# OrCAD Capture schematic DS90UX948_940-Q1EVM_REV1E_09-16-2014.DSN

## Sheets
1 08. Revision History: title: Revision History; rev: 1E; note: DS90UBUH948_940-Q1EVM
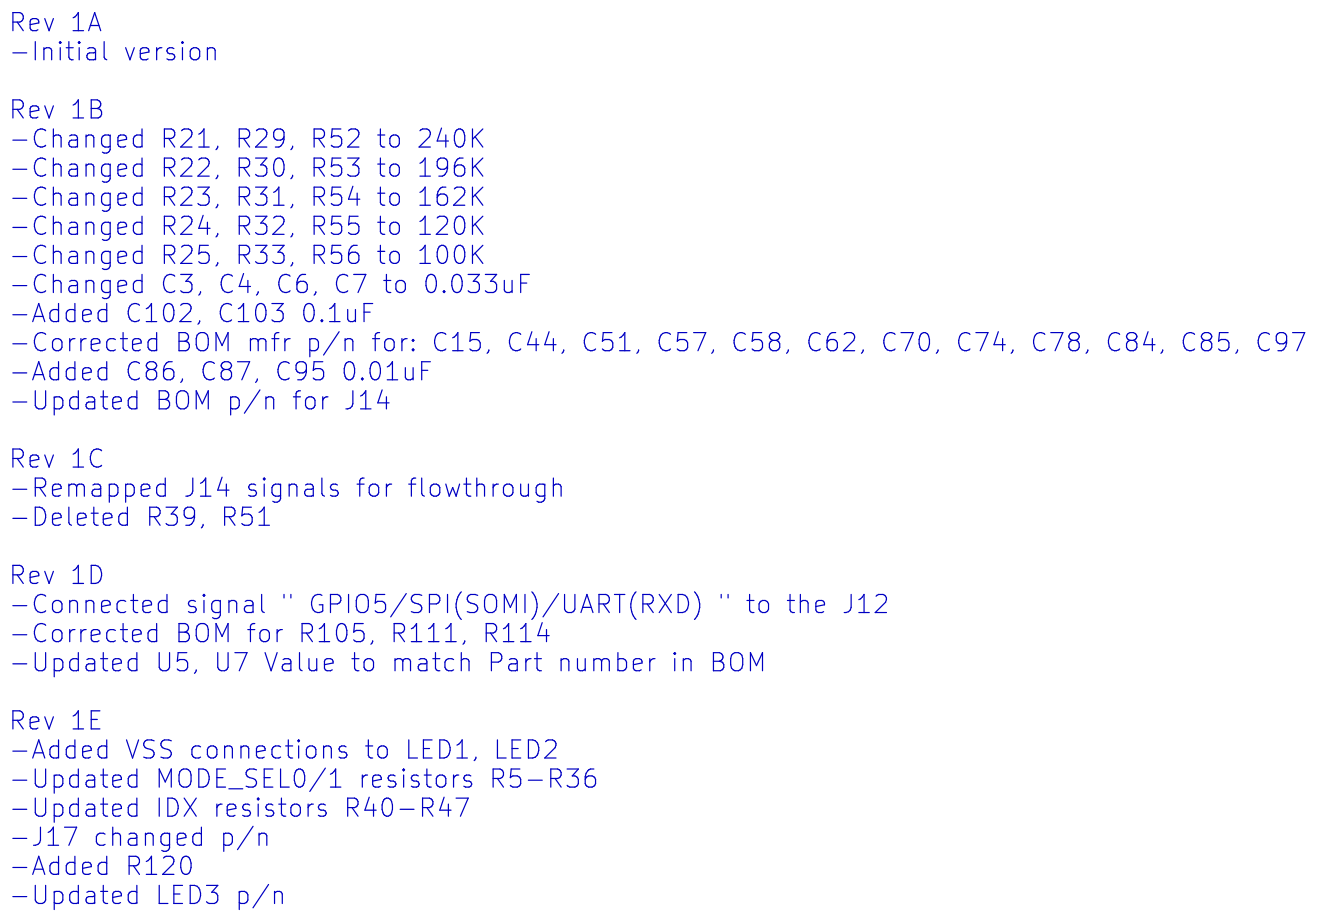
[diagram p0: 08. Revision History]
2 02. Block Diagram: title: Block Diagram
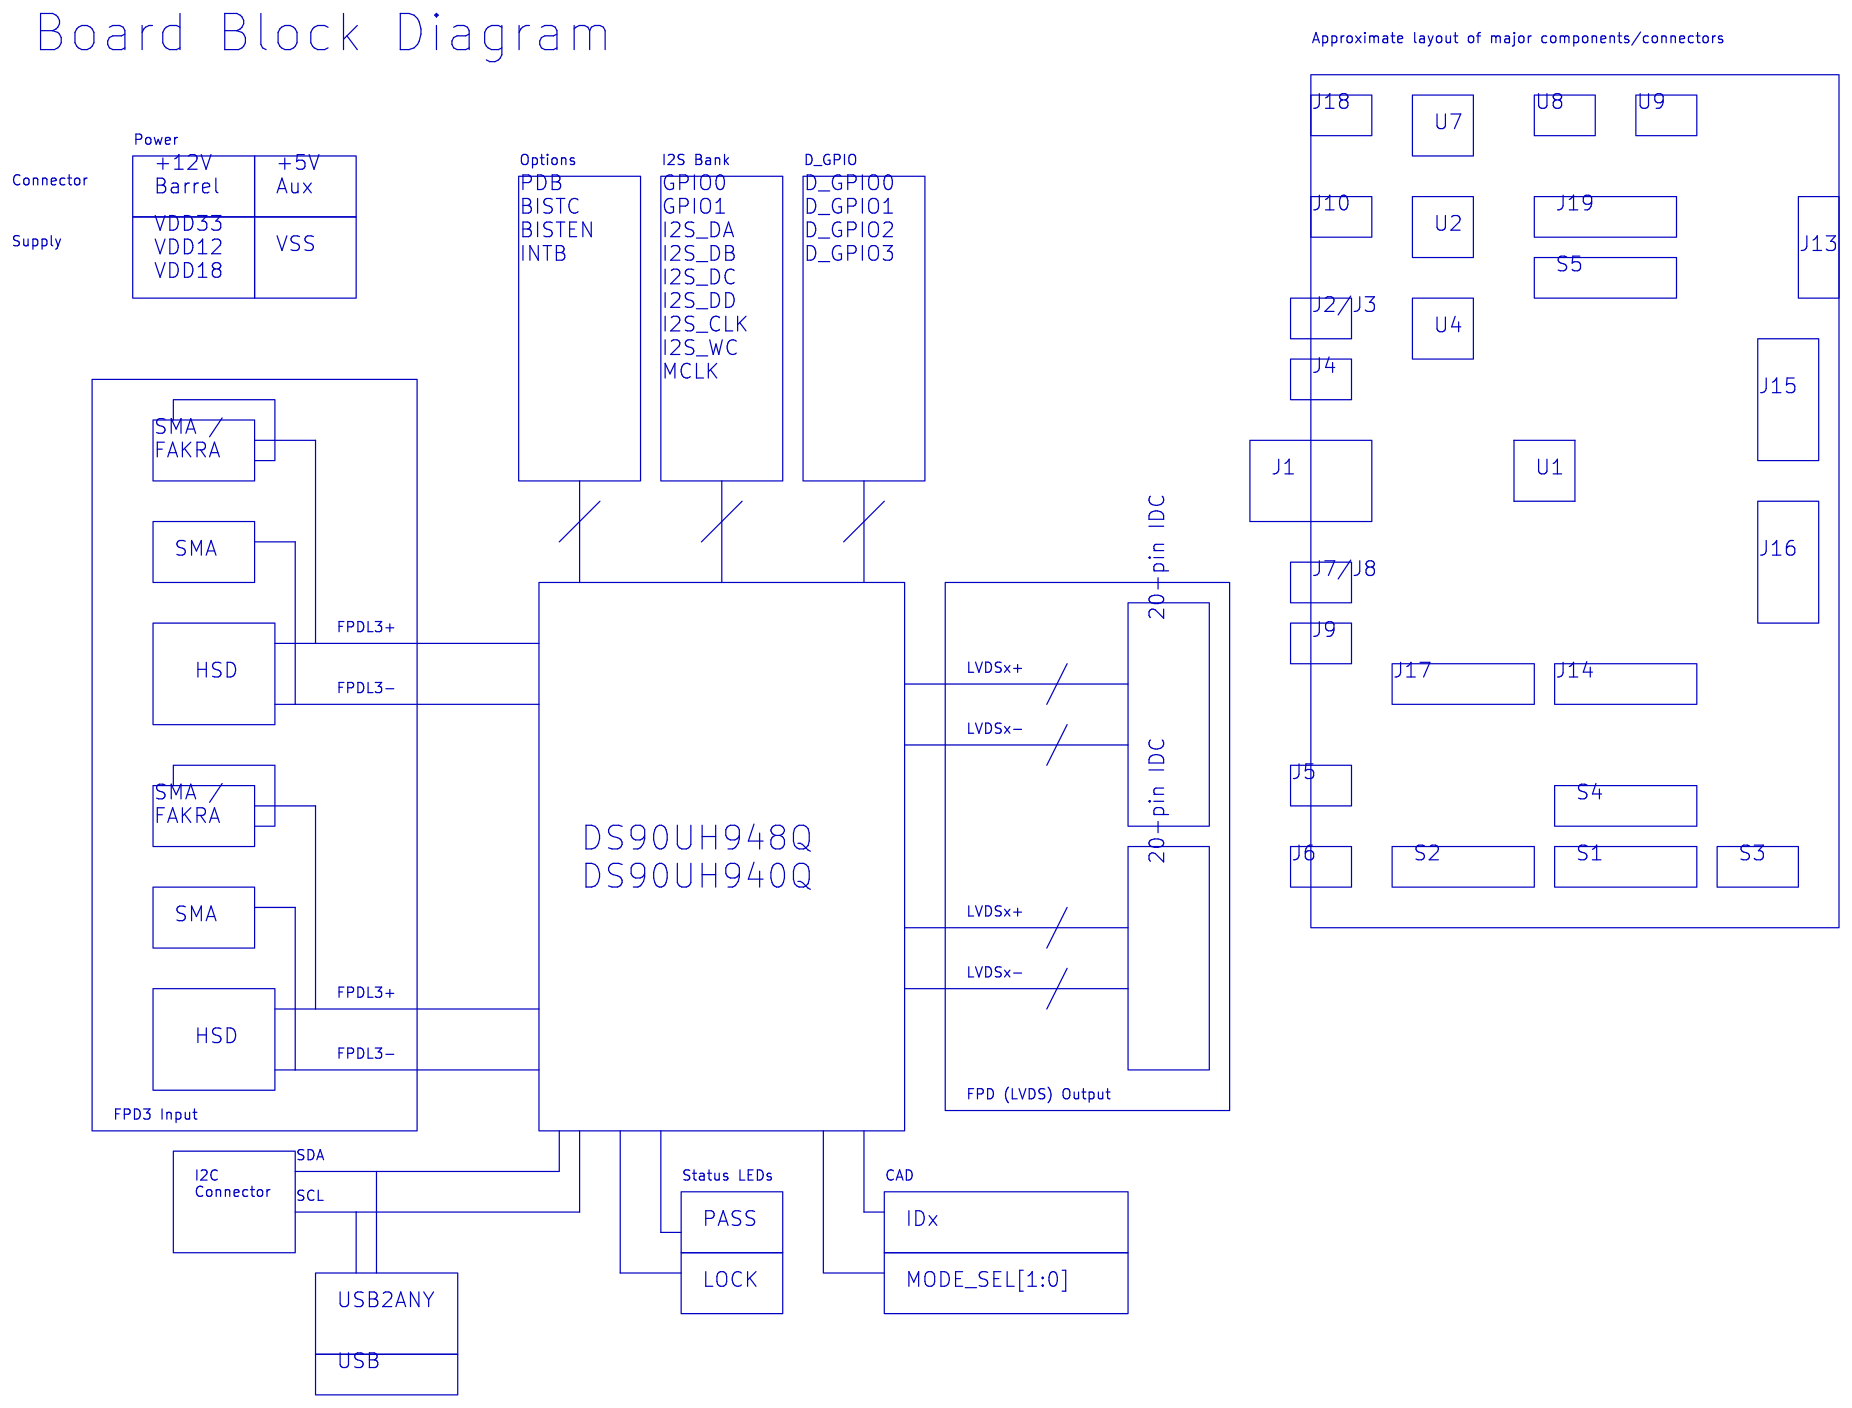
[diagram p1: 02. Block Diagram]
3 01. Board Stackup: title: Board Stackup
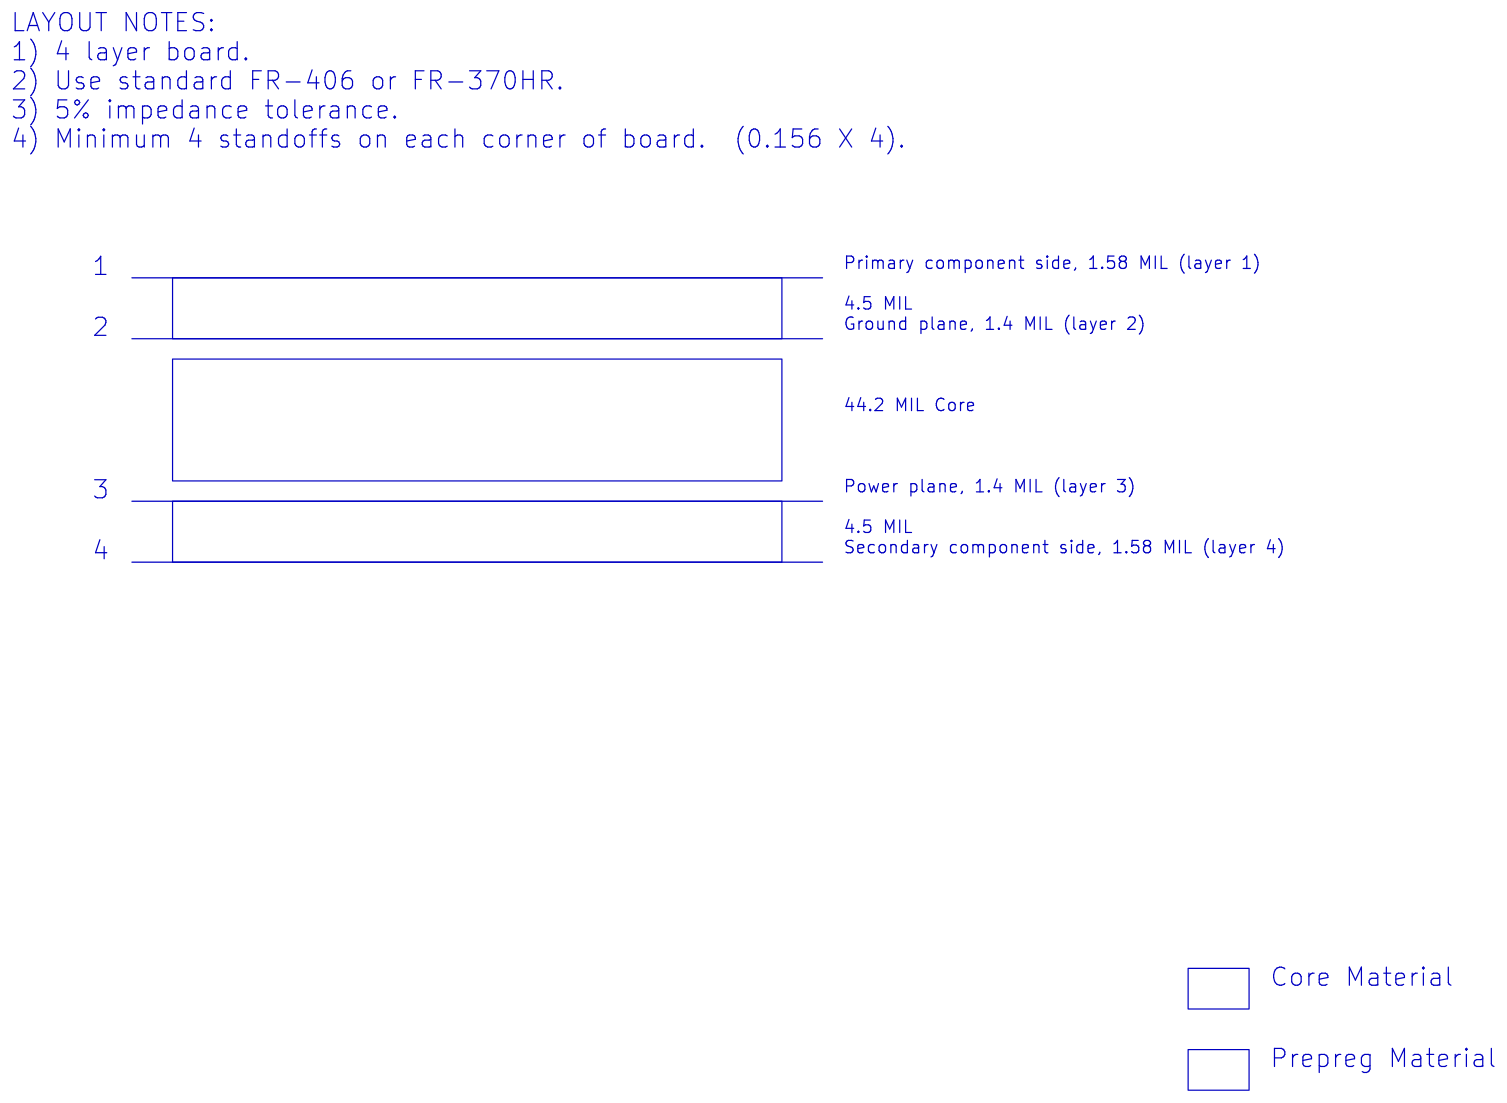
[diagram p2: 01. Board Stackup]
4 03. DS90UH948Q: size B; title: DS90UBUH948
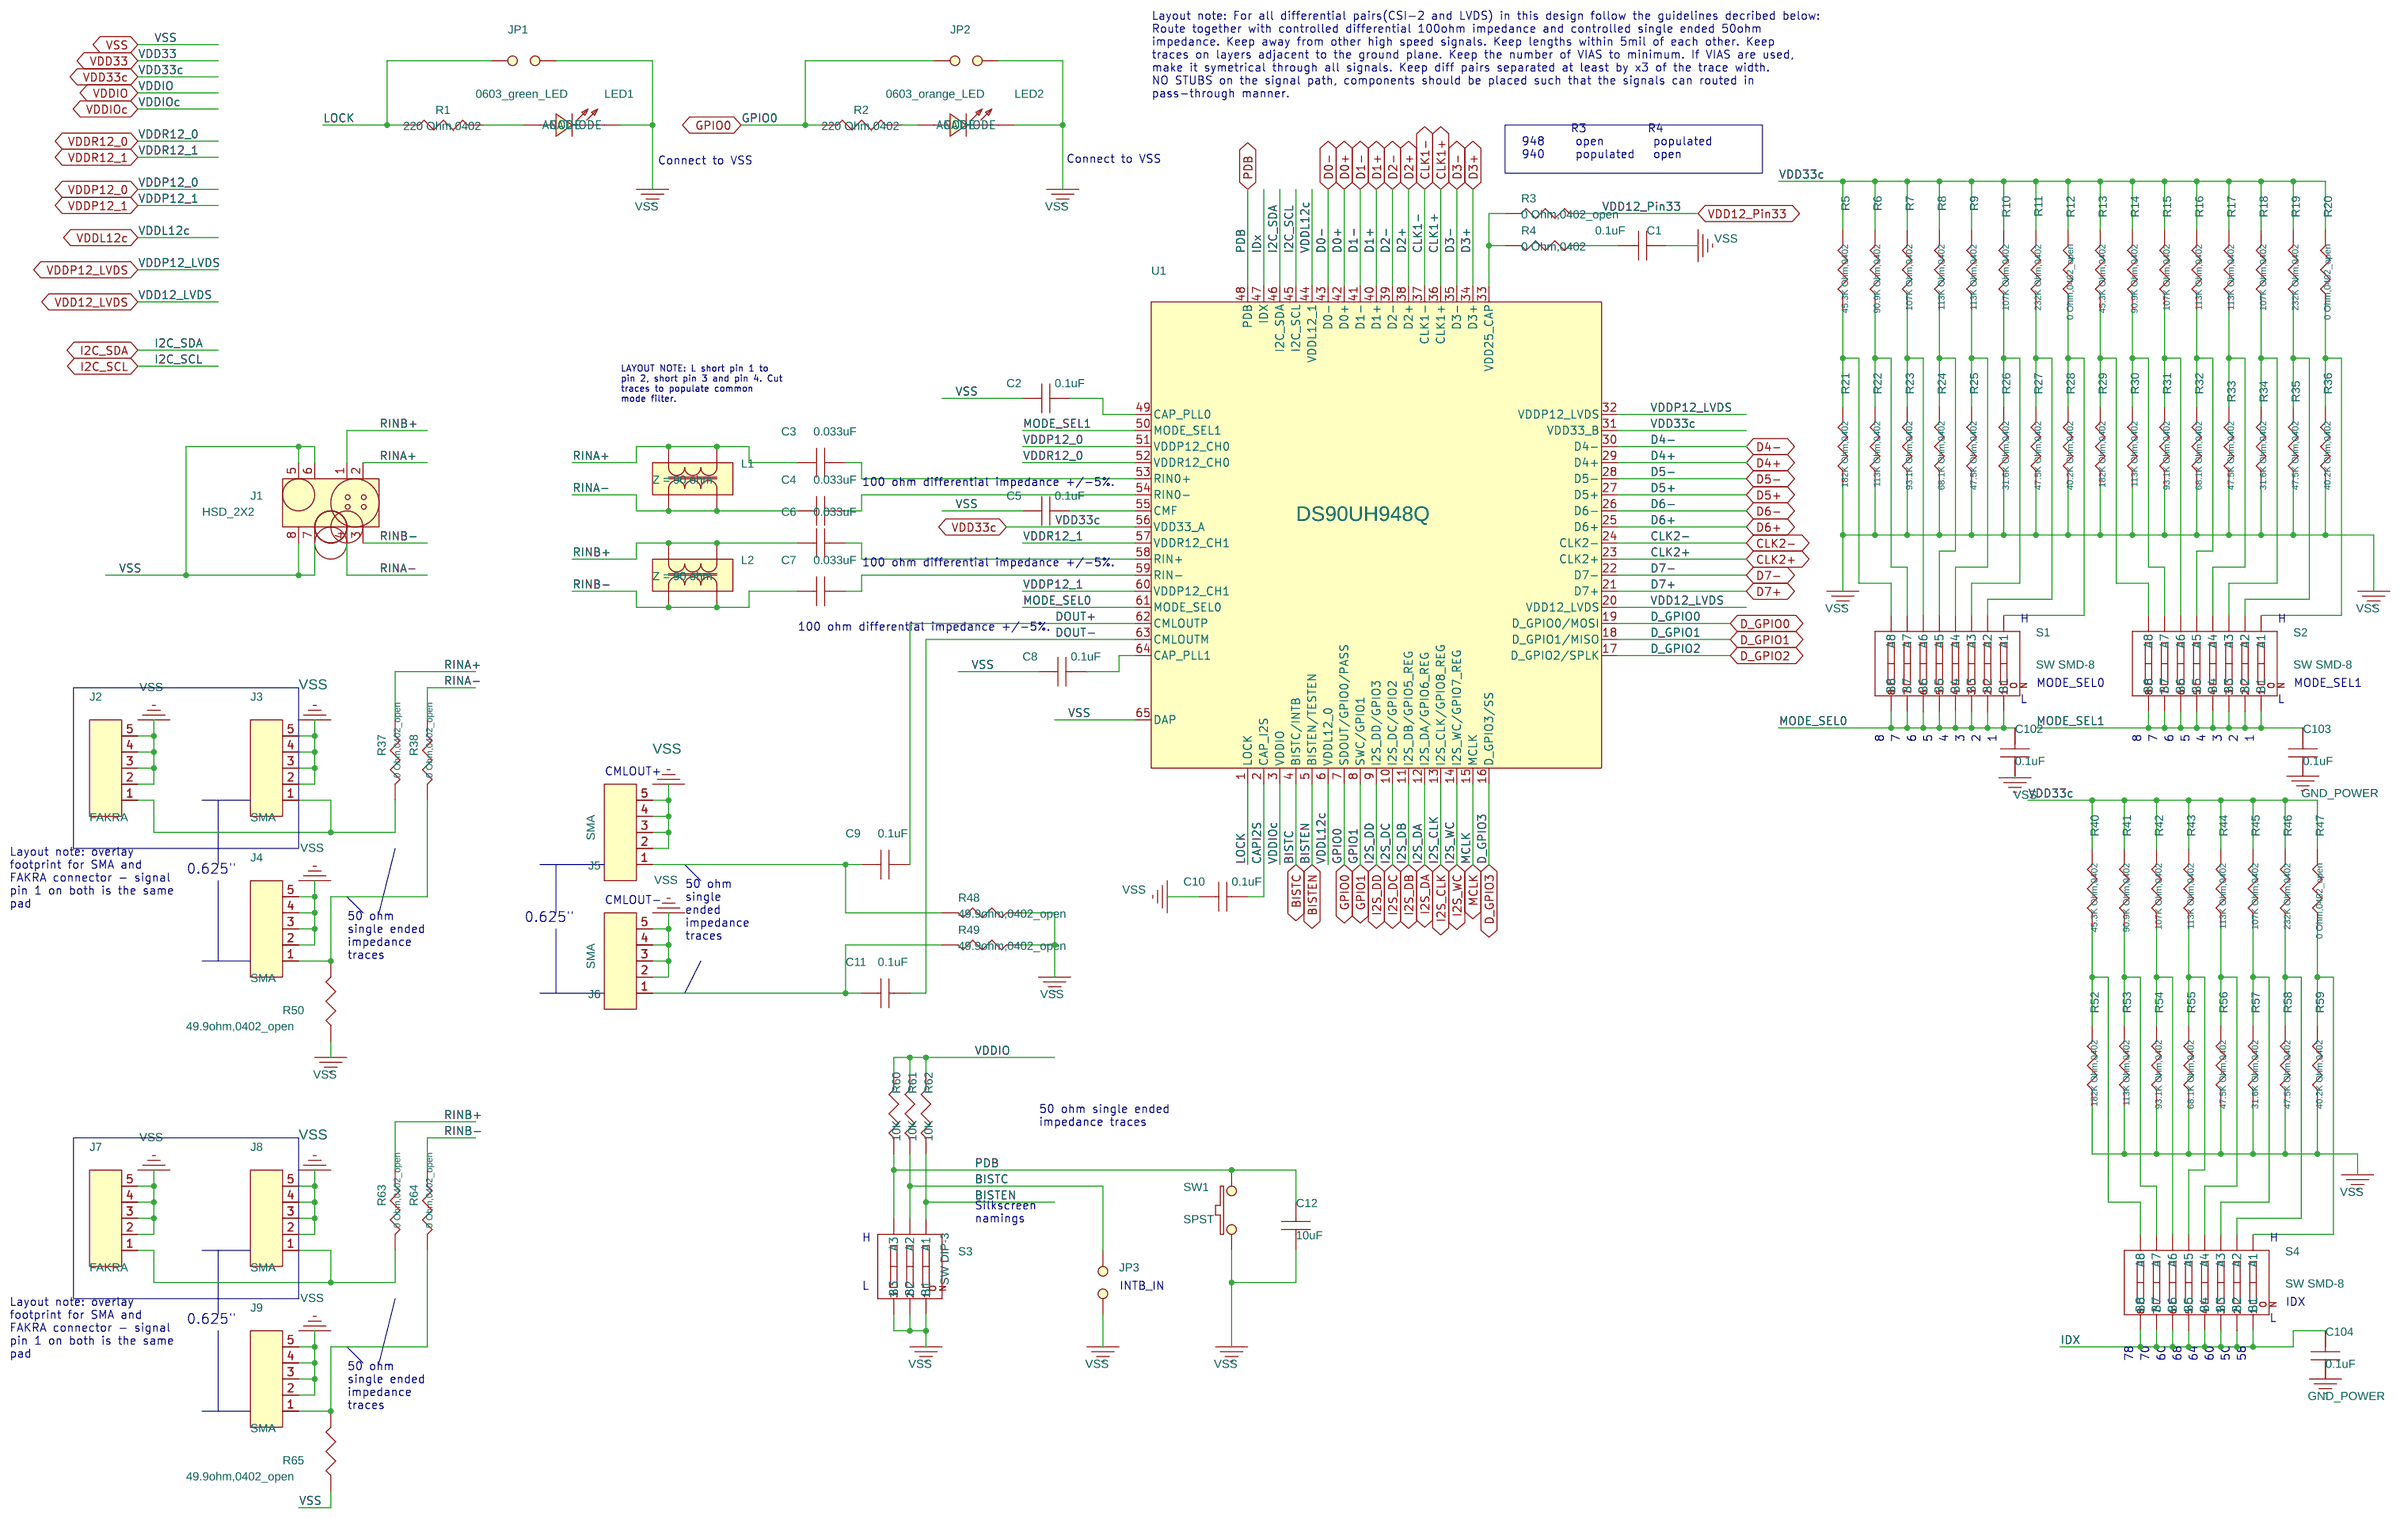
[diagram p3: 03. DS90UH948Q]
5 04. USB Controller: size C; title: USB Controller
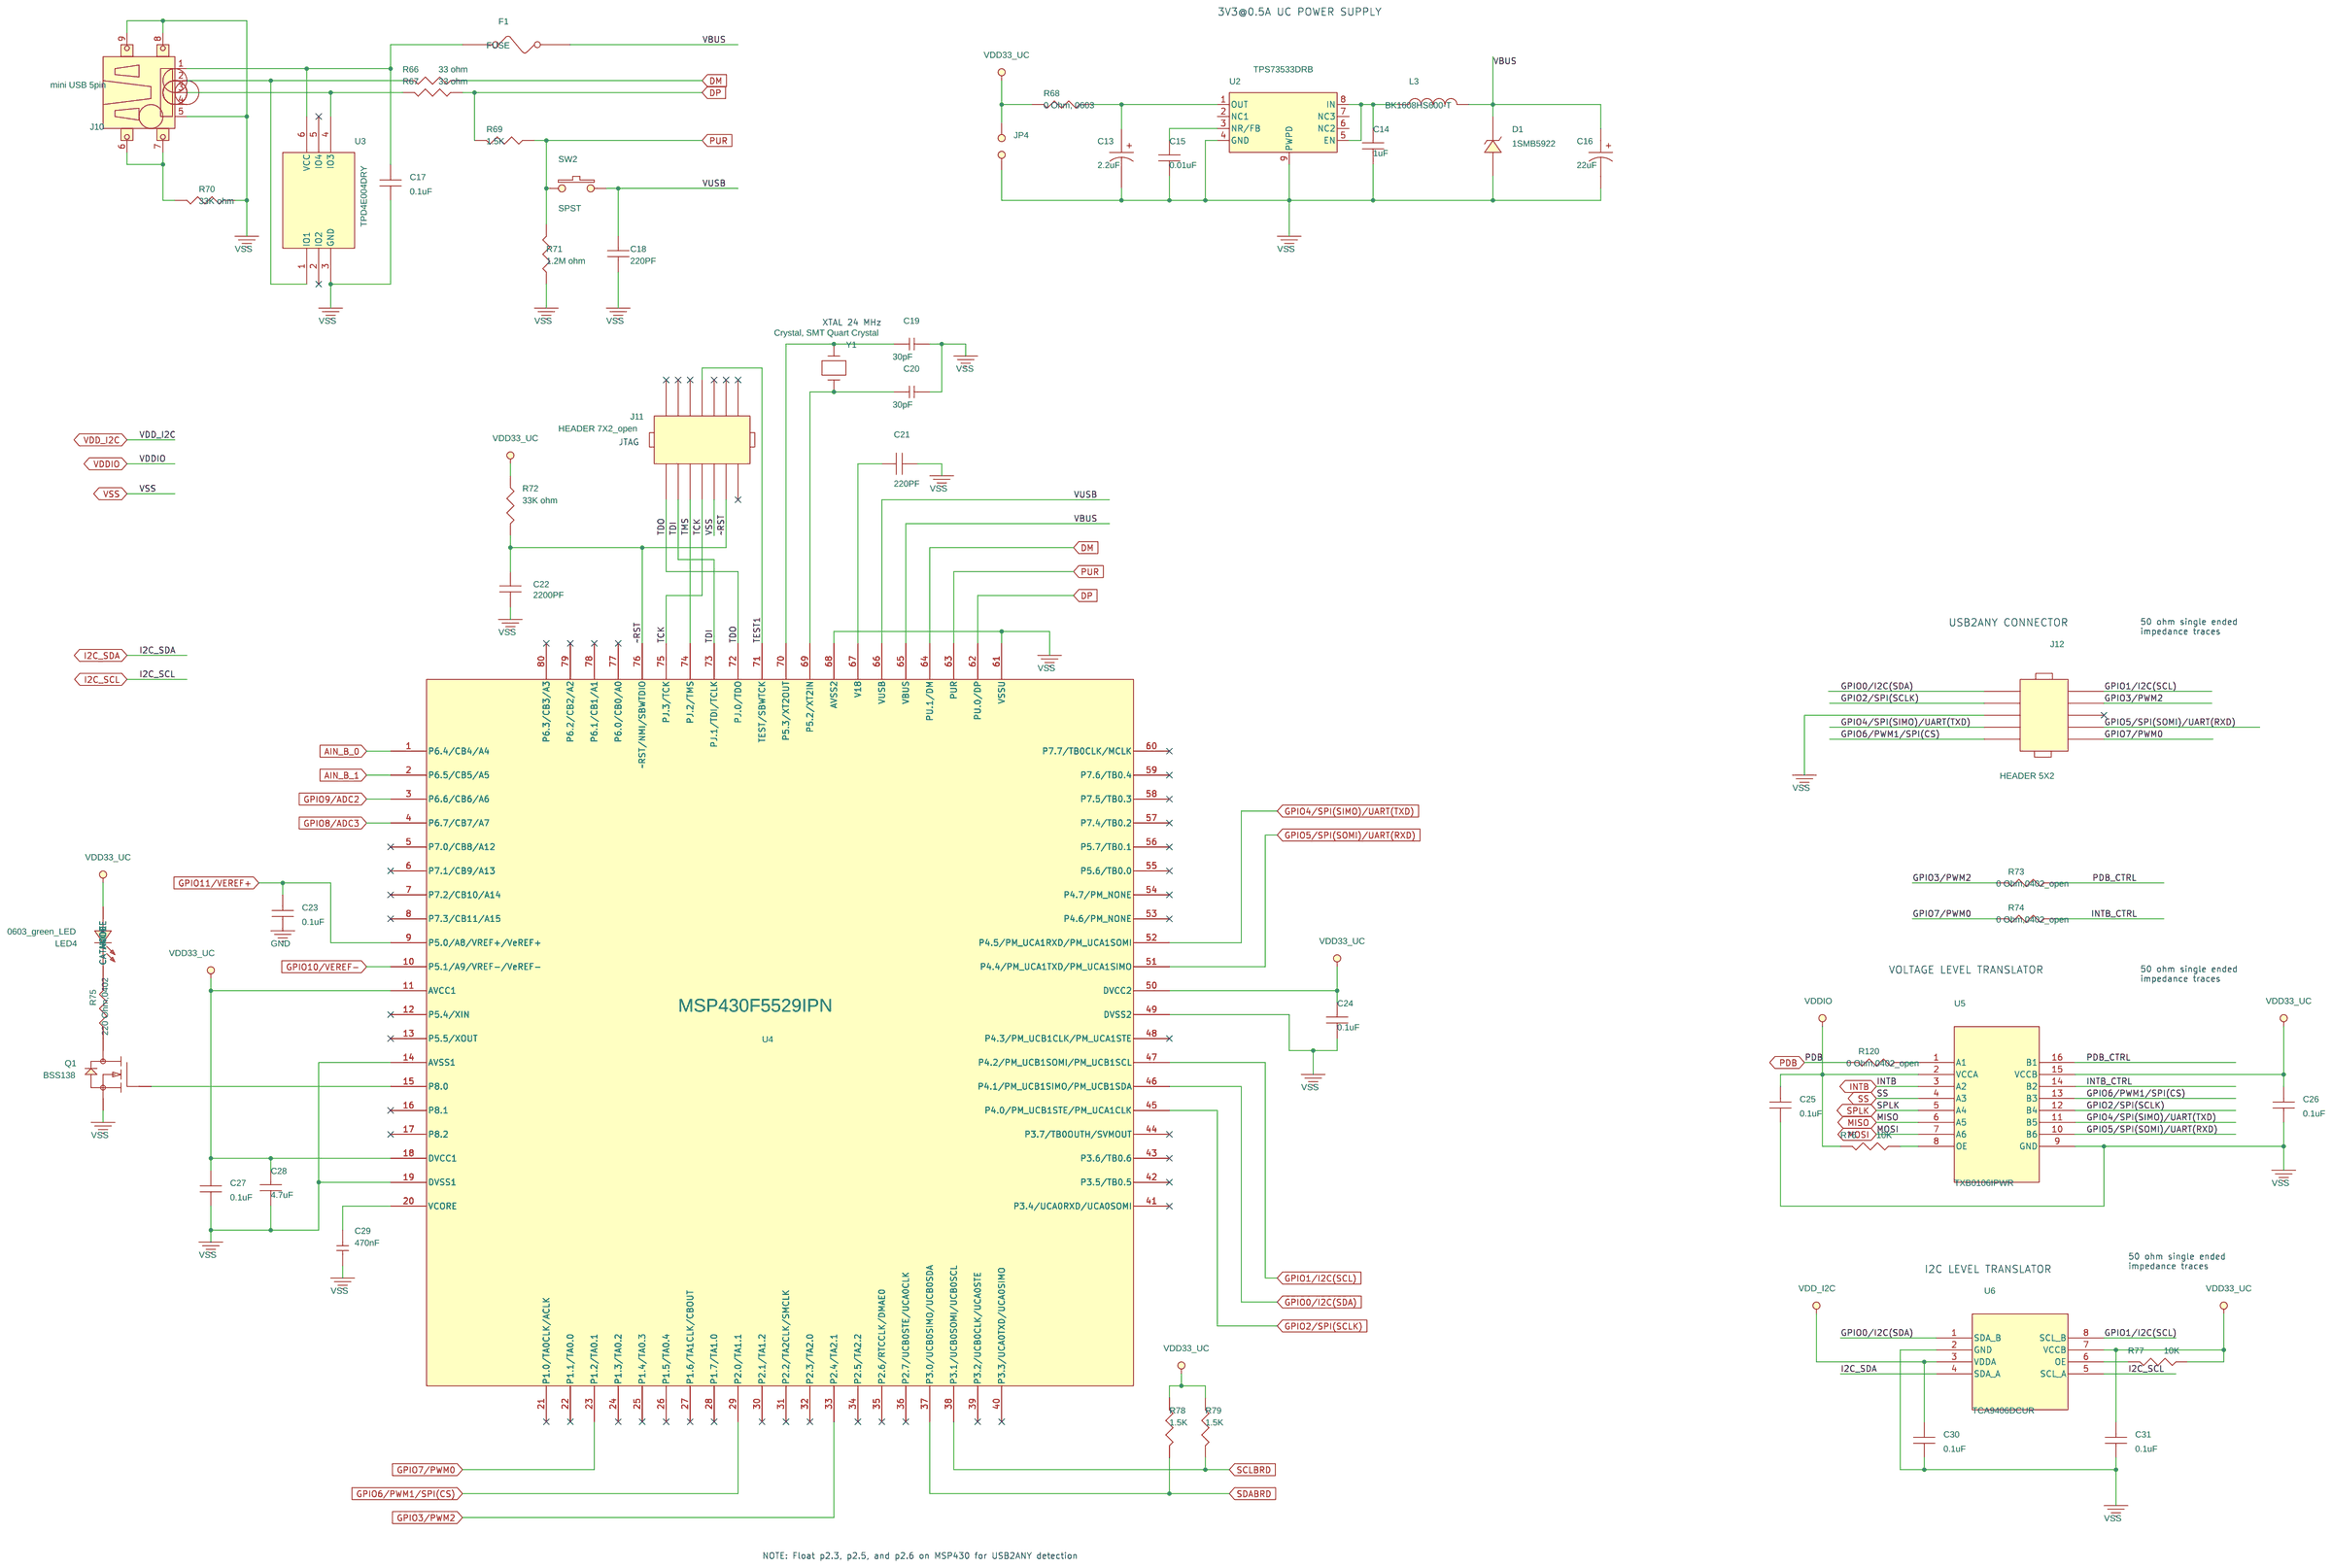
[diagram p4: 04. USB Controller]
6 05. Output and Termination: size B; title: Output and Termination
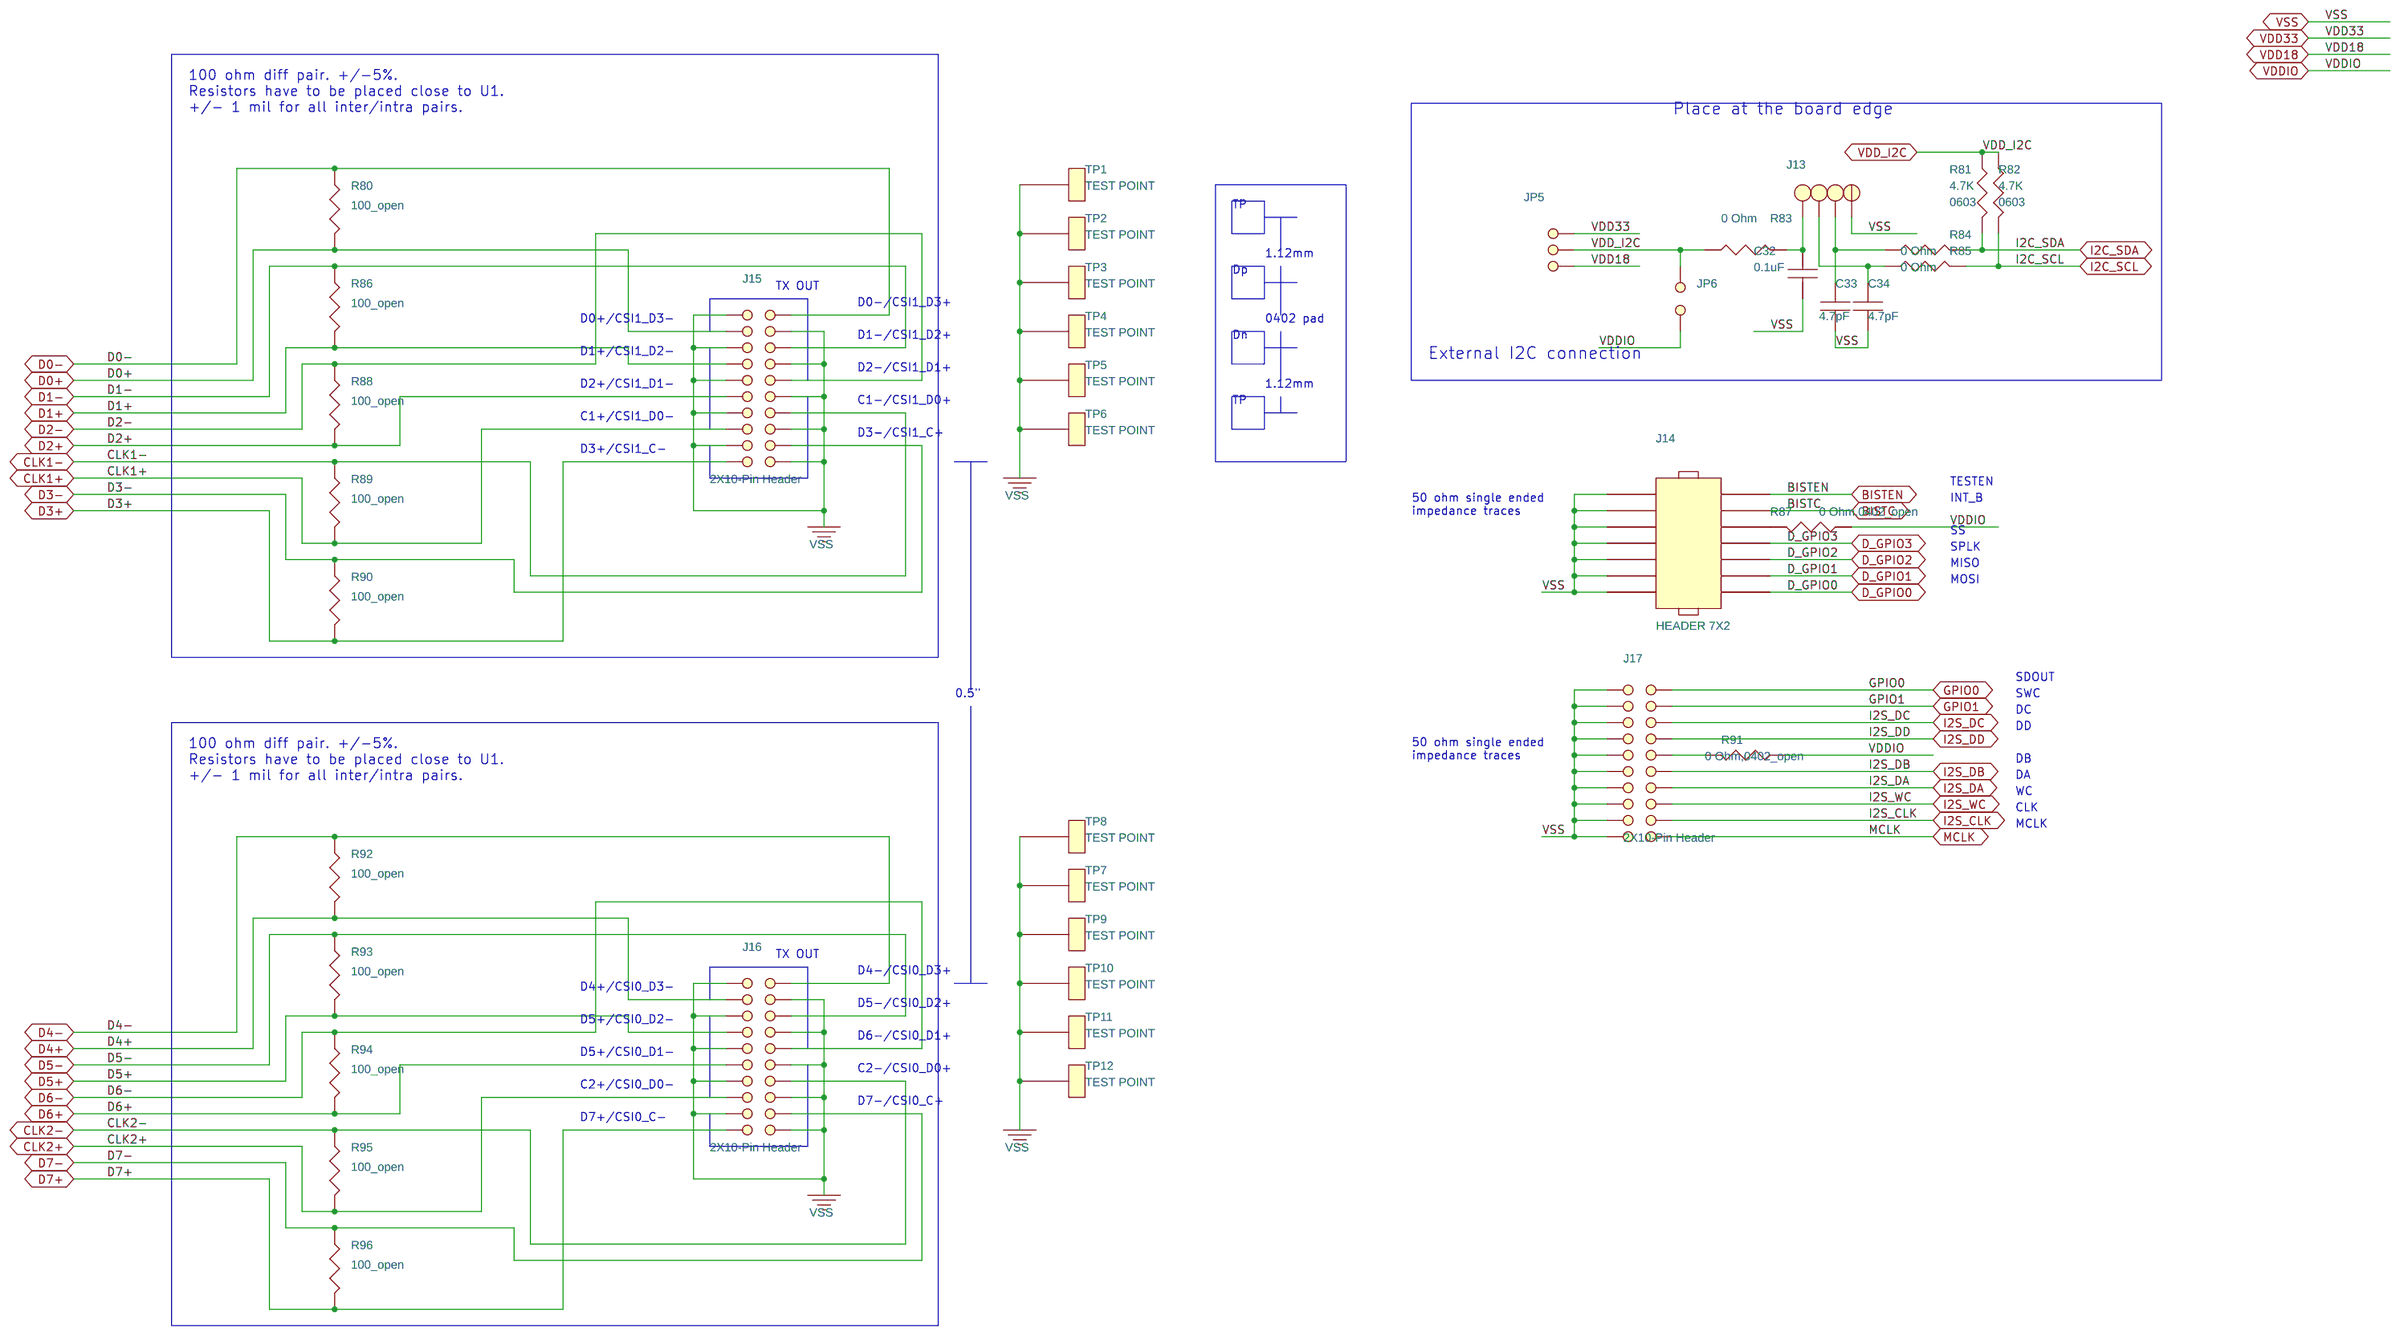
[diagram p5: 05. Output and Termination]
7 06. PWR and Decoupling: size B; title: Power and Decoupling
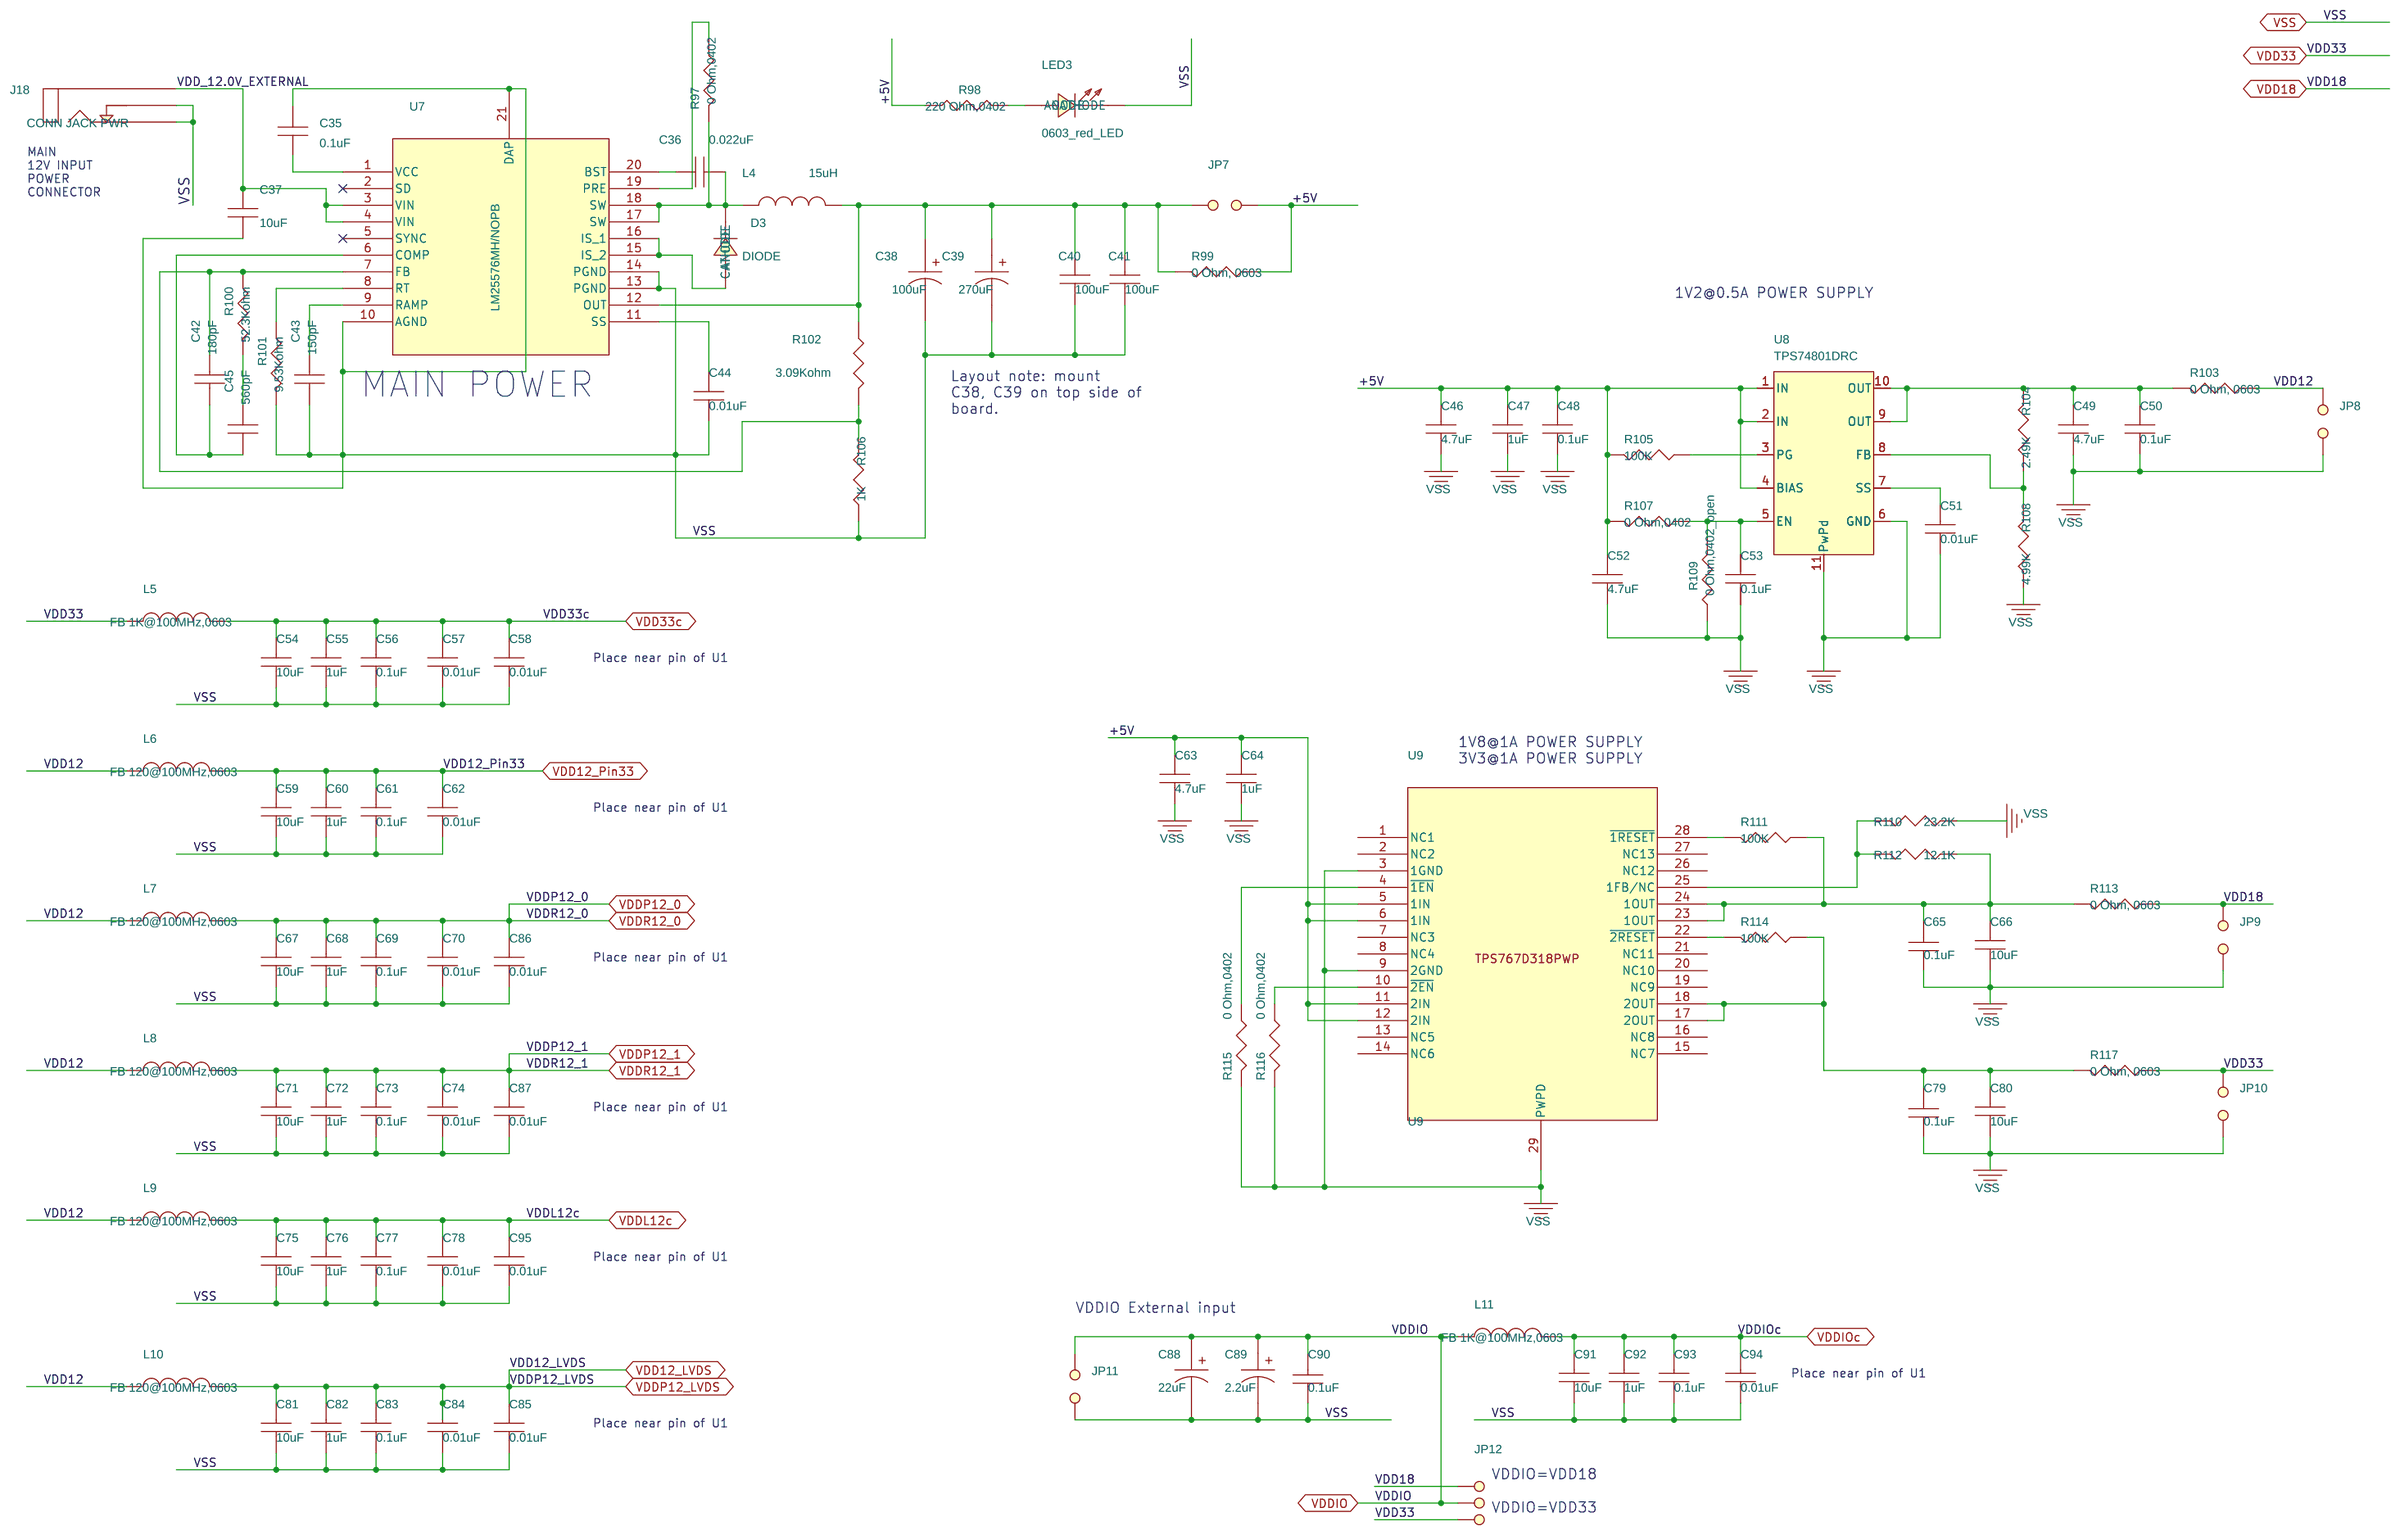
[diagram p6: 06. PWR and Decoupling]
8 07. EXT MSP430: size A; title: External MSP430 Controller
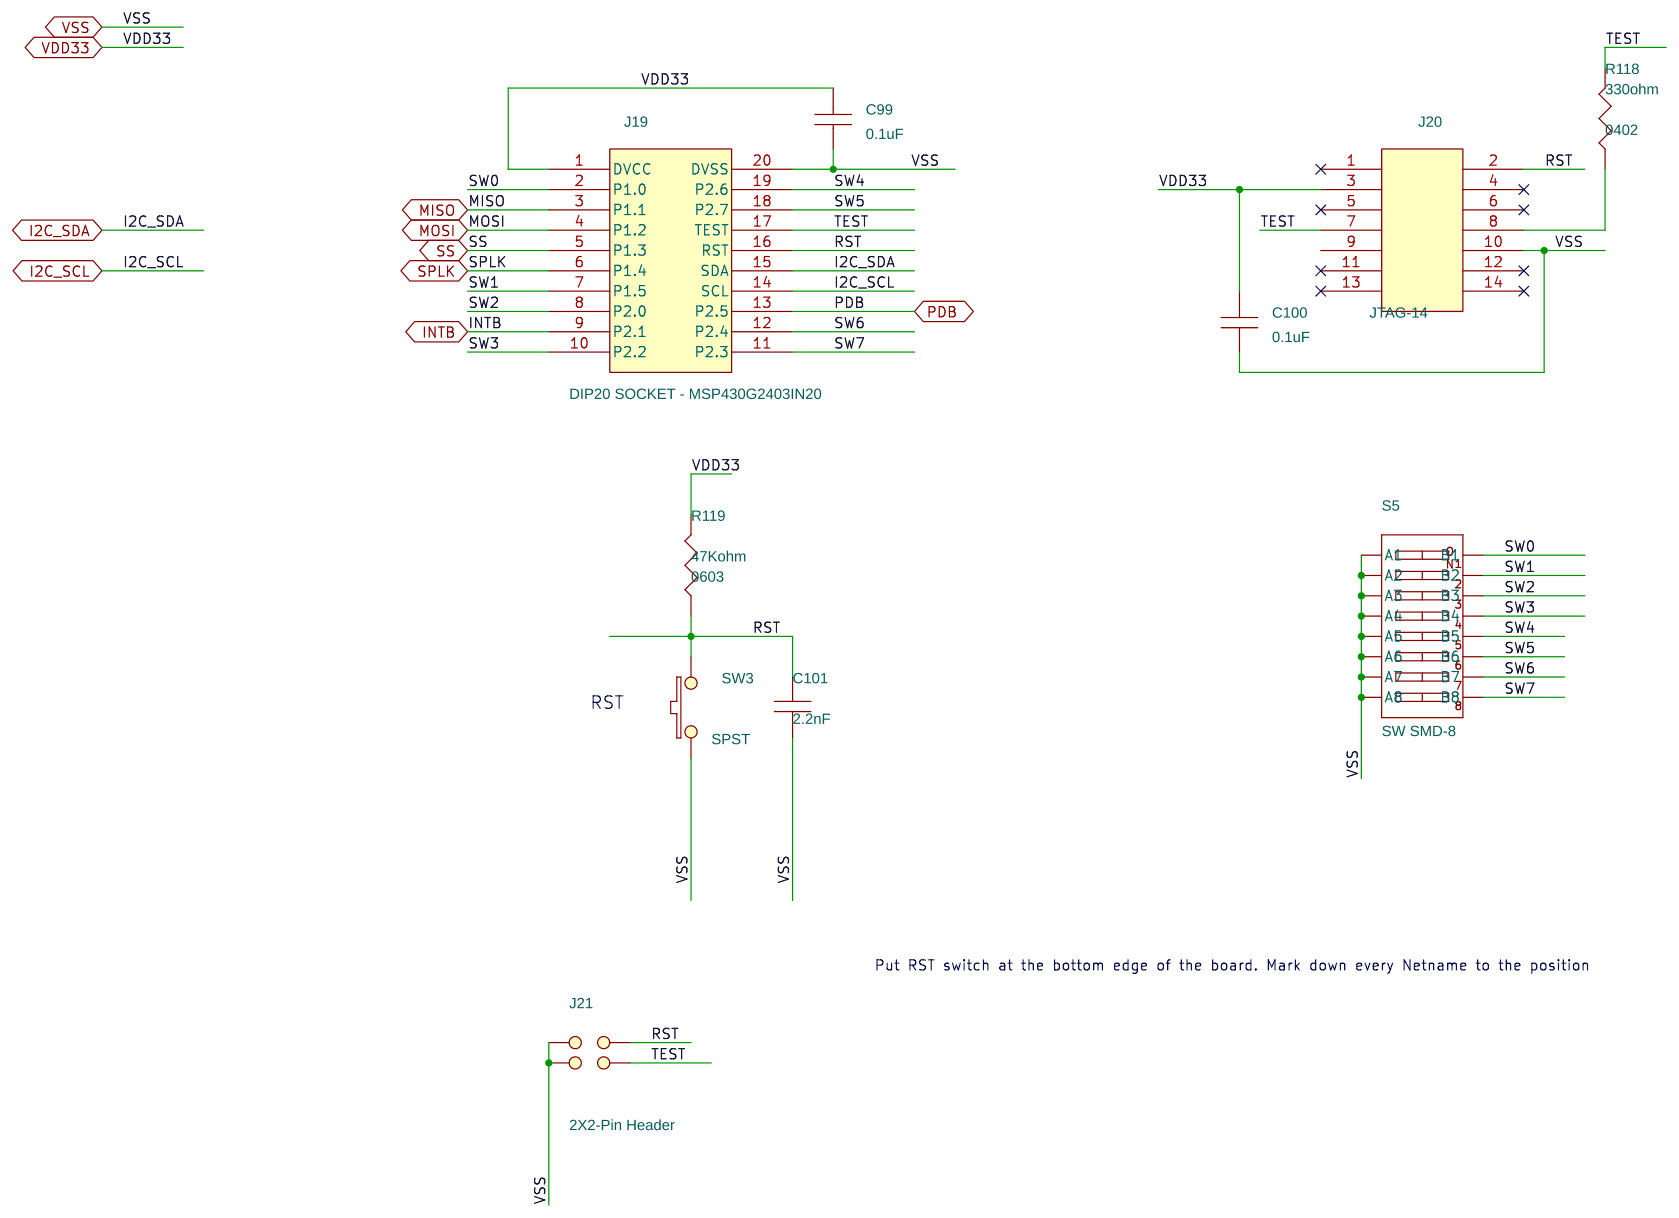
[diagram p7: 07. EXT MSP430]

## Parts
sheet 03. DS90UH948Q
C1  0.1uF  [0402_1005_Metric]
C2  0.1uF  [0402_1005_Metric]
C3  0.033uF  [0402_1005_Metric]
C4  0.033uF  [0402_1005_Metric]
C5  0.1uF  [0402_1005_Metric]
C6  0.033uF  [0402_1005_Metric]
C7  0.033uF  [0402_1005_Metric]
C8  0.1uF  [0402_1005_Metric]
C9  0.1uF  [0402_1005_Metric]
C10  0.1uF  [0402_1005_Metric]
C11  0.1uF  [0402_1005_Metric]
C12  10uF  [1206_3216_Metric]
C102  0.1uF  [0402_1005_Metric]
C103  0.1uF  [0402_1005_Metric]
C104  0.1uF  [0402_1005_Metric]
J1  HSD_2X2  [CON_HSD-4P]
J2  FAKRA  [59S20X-40ML5-Y]
J3  SMA  [Edge_mount]
J4  SMA  [Edge_mount]
J5  SMA  [Edge_mount]
J6  SMA  [Edge_mount]
J7  FAKRA  [59S20X-40ML5-Y]
J8  SMA  [Edge_mount]
J9  SMA  [Edge_mount]
JP1  2-Pin Header_open  [Header_2P]
JP2  2-Pin Header_open  [Header_2P]
JP3  2-Pin Header_open  [Header_2P]
L1  Z = 90 ohm  [L_HDC-0805]
L2  Z = 90 ohm  [L_HDC-0805]
LED1  0603_green_LED  [d-0603]
LED2  0603_orange_LED  [0603_SMT]
R1  220 Ohm,0402  [RES_HDC-0402]
R2  220 Ohm,0402  [RES_HDC-0402]
R3  0 Ohm,0402_open  [RES_HDC-0402]
R4  0 Ohm,0402  [RES_HDC-0402]
R5  45.3K Ohm,0402  [RES_HDC-0402]
R6  90.9K Ohm,0402  [RES_HDC-0402]
R7  107K Ohm,0402  [RES_HDC-0402]
R8  113K Ohm,0402  [RES_HDC-0402]
R9  113K Ohm,0402  [RES_HDC-0402]
R10  107K Ohm,0402  [RES_HDC-0402]
R11  232K Ohm,0402  [RES_HDC-0402]
R12  0 Ohm,0402_open  [RES_HDC-0402]
R13  45.3K Ohm,0402  [RES_HDC-0402]
R14  90.9K Ohm,0402  [RES_HDC-0402]
R15  107K Ohm,0402  [RES_HDC-0402]
R16  113K Ohm,0402  [RES_HDC-0402]
R17  113K Ohm,0402  [RES_HDC-0402]
R18  107K Ohm,0402  [RES_HDC-0402]
R19  232K Ohm,0402  [RES_HDC-0402]
R20  0 Ohm,0402_open  [RES_HDC-0402]
R21  182K Ohm,0402  [RES_HDC-0402]
R22  113K Ohm,0402  [RES_HDC-0402]
R23  93.1K Ohm,0402  [RES_HDC-0402]
R24  68.1K Ohm,0402  [RES_HDC-0402]
R25  47.5K Ohm,0402  [RES_HDC-0402]
R26  31.6K Ohm,0402  [RES_HDC-0402]
R27  47.5K Ohm,0402  [RES_HDC-0402]
R28  40.2K Ohm,0402  [RES_HDC-0402]
R29  182K Ohm,0402  [RES_HDC-0402]
R30  113K Ohm,0402  [RES_HDC-0402]
R31  93.1K Ohm,0402  [RES_HDC-0402]
R32  68.1K Ohm,0402  [RES_HDC-0402]
R33  47.5K Ohm,0402  [RES_HDC-0402]
R34  31.6K Ohm,0402  [RES_HDC-0402]
R35  47.5K Ohm,0402  [RES_HDC-0402]
R36  40.2K Ohm,0402  [RES_HDC-0402]
R37  0 Ohm,0402_open  [RES_HDC-0402]
R38  0 Ohm,0402_open  [RES_HDC-0402]
R40  45.3K Ohm,0402  [RES_HDC-0402]
R41  90.9K Ohm,0402  [RES_HDC-0402]
R42  107K Ohm,0402  [RES_HDC-0402]
R43  113K Ohm,0402  [RES_HDC-0402]
R44  113K Ohm,0402  [RES_HDC-0402]
R45  107K Ohm,0402  [RES_HDC-0402]
R46  232K Ohm,0402  [RES_HDC-0402]
R47  0 Ohm,0402_open  [RES_HDC-0402]
R48  49.9ohm,0402_open  [RES_HDC-0402]
R49  49.9ohm,0402_open  [RES_HDC-0402]
R50  49.9ohm,0402_open  [RES_HDC-0402]
R52  182K Ohm,0402  [RES_HDC-0402]
R53  113K Ohm,0402  [RES_HDC-0402]
R54  93.1K Ohm,0402  [RES_HDC-0402]
R55  68.1K Ohm,0402  [RES_HDC-0402]
R56  47.5K Ohm,0402  [RES_HDC-0402]
R57  31.6K Ohm,0402  [RES_HDC-0402]
R58  47.5K Ohm,0402  [RES_HDC-0402]
R59  40.2K Ohm,0402  [RES_HDC-0402]
R60  10K  [RES_HDC-0603]
R61  10K  [RES_HDC-0603]
R62  10K  [RES_HDC-0603]
R63  0 Ohm,0402_open  [RES_HDC-0402]
R64  0 Ohm,0402_open  [RES_HDC-0402]
R65  49.9ohm,0402_open  [RES_HDC-0402]
S1  SW SMD-8  [SMD-20]
S2  SW SMD-8  [SMD-20]
S3  SW DIP-3  [DIP-6]
S4  SW SMD-8  [SMD-20]
SW1  SPST  [ADTSM31NV]
U1  DS90UH948Q  [WQFN-64]
sheet 04. USB Controller
C13  2.2uF  [3528-21_EIA]
C14  1uF  [0603_1608_Metric]
C15  0.01uF  [0402_1005_Metric]
C16  22uF  [CAP_N]
C17  0.1uF  [0402_1005_Metric]
C18  220PF  [0603]
C19  30pF  [0603]
C20  30pF  [0603]
C21  220PF  [0603]
C22  2200PF  [0603]
C23  0.1uF  [0402_1005_Metric]
C24  0.1uF  [0402_1005_Metric]
C25  0.1uF  [0402_1005_Metric]
C26  0.1uF  [0402_1005_Metric]
C27  0.1uF  [0402_1005_Metric]
C28  4.7uF  [0805_2012_Metric]
C29  470nF  [0603]
C30  0.1uF  [0402_1005_Metric]
C31  0.1uF  [0402_1005_Metric]
D1  1SMB5922  [DO-214AA_SMB]
F1  FUSE  [1206]
J10  mini USB 5pin  [mini_B_USB_surface_mount]
J11  HEADER 7X2_open  [0_100inchx2X7]
J12  HEADER 5X2  [Through_Hole]
JP4  2-Pin Header  [Header_2P]
L3  BK1608HS600-T  [L0603]
LED4  0603_green_LED  [d-0603]
Q1  BSS138  [SOT23]
R66  33 ohm  [RES_0603]
R67  33 ohm  [RES_0603]
R68  0 Ohm, 0603  [R0603_1608_Metric]
R69  1.5K  [0603]
R70  33K ohm  [0603]
R71  1.2M ohm  [0603]
R72  33K ohm  [0603]
R73  0 Ohm,0402_open  [RES_HDC-0402]
R74  0 Ohm,0402_open  [RES_HDC-0402]
R75  220 Ohm,0402  [RES_HDC-0402]
R76  10K  [RES_HDC-0603]
R77  10K  [RES_HDC-0603]
R78  1.5K  [0603]
R79  1.5K  [0603]
R120  0 Ohm,0402_open  [RES_HDC-0402]
SW2  SPST  [ADTSM31NV]
U2  TPS73533DRB  [TPS73533DRBT]
U3  TPD4E004DRY  [SON-6]
U4  MSP430F5529IPN  [TQFP-80]
U5  TXB0106IPWR  [16TSSOP]
U6  TCA9406DCUR  [8-VFSOP_0p091_2p30mm_Width]
Y1  Crystal, SMT Quart Crystal  [0_484x0_190_inch]
sheet 05. Output and Termination
C32  0.1uF  [0402_1005_Metric]
C33  4.7pF  [C-0402]
C34  4.7pF  [C-0402]
J13  IDC1X4  [IDC-1x4]
J14  HEADER 7X2  [0_100inchx2X7]
J15  2X10-Pin Header  [N2520_6002RB]
J16  2X10-Pin Header  [N2520_6002RB]
J17  2X10-Pin Header  [Header_2X10P]
JP5  3-Pin Header  [Header_3P]
JP6  2-Pin Header  [Header_2P]
R80  100_open  [RES_HDC-0402]
R81  4.7K  [R-0603]
R82  4.7K  [R-0603]
R83  0 Ohm  [R-0402]
R84  0 Ohm  [R-0402]
R85  0 Ohm  [R-0402]
R86  100_open  [RES_HDC-0402]
R87  0 Ohm,0402_open  [RES_HDC-0402]
R88  100_open  [RES_HDC-0402]
R89  100_open  [RES_HDC-0402]
R90  100_open  [RES_HDC-0402]
R91  0 Ohm,0402_open  [RES_HDC-0402]
R92  100_open  [RES_HDC-0402]
R93  100_open  [RES_HDC-0402]
R94  100_open  [RES_HDC-0402]
R95  100_open  [RES_HDC-0402]
R96  100_open  [RES_HDC-0402]
TP1  TEST POINT  [TEST_POINT]
TP2  TEST POINT  [TEST_POINT]
TP3  TEST POINT  [TEST_POINT]
TP4  TEST POINT  [TEST_POINT]
TP5  TEST POINT  [TEST_POINT]
TP6  TEST POINT  [TEST_POINT]
TP7  TEST POINT  [TEST_POINT]
TP8  TEST POINT  [TEST_POINT]
TP9  TEST POINT  [TEST_POINT]
TP10  TEST POINT  [TEST_POINT]
TP11  TEST POINT  [TEST_POINT]
TP12  TEST POINT  [TEST_POINT]
sheet 06. PWR and Decoupling
C35  0.1uF  [0402_1005_Metric]
C36  0.022uF  [CAP_HDC-0805_2012_Metric]
C37  10uF  [1210_3225_Metric]
C38  100uF  [CAP_7343-31_EIA]
C39  270uF  [CAP_0p327Lx0p327W_8p30mmx8p30mm]
C40  100uF  [CAP_HDC-1210_3225_Metric]
C41  100uF  [CAP_HDC-1210_3225_Metric]
C42  180pF  [CAP_HDC-0805_2012_Metric]
C43  150pF  [CAP_HDC-0805_2012_Metric]
C44  0.01uF  [0402_1005_Metric]
C45  560pF  [CAP_HDC-0805_2012_Metric]
C46  4.7uF  [0805_2012_Metric]
C47  1uF  [0603_1608_Metric]
C48  0.1uF  [0402_1005_Metric]
C49  4.7uF  [0805_2012_Metric]
C50  0.1uF  [0402_1005_Metric]
C51  0.01uF  [0402_1005_Metric]
C52  4.7uF  [0805_2012_Metric]
C53  0.1uF  [0402_1005_Metric]
C54  10uF  [0805_2012_Metric]
C55  1uF  [0603_1608_Metric]
C56  0.1uF  [0402_1005_Metric]
C57  0.01uF  [0402_1005_Metric]
C58  0.01uF  [0402_1005_Metric]
C59  10uF  [0805_2012_Metric]
C60  1uF  [0603_1608_Metric]
C61  0.1uF  [0402_1005_Metric]
C62  0.01uF  [0402_1005_Metric]
C63  4.7uF  [0805_2012_Metric]
C64  1uF  [0603_1608_Metric]
C65  0.1uF  [0402_1005_Metric]
C66  10uF  [1206_3216_Metric]
C67  10uF  [0805_2012_Metric]
C68  1uF  [0603_1608_Metric]
C69  0.1uF  [0402_1005_Metric]
C70  0.01uF  [0402_1005_Metric]
C71  10uF  [0805_2012_Metric]
C72  1uF  [0603_1608_Metric]
C73  0.1uF  [0402_1005_Metric]
C74  0.01uF  [0402_1005_Metric]
C75  10uF  [0805_2012_Metric]
C76  1uF  [0603_1608_Metric]
C77  0.1uF  [0402_1005_Metric]
C78  0.01uF  [0402_1005_Metric]
C79  0.1uF  [0402_1005_Metric]
C80  10uF  [1206_3216_Metric]
C81  10uF  [0805_2012_Metric]
C82  1uF  [0603_1608_Metric]
C83  0.1uF  [0402_1005_Metric]
C84  0.01uF  [0402_1005_Metric]
C85  0.01uF  [0402_1005_Metric]
C86  0.01uF  [0402_1005_Metric]
C87  0.01uF  [0402_1005_Metric]
C88  22uF  [CAP_N]
C89  2.2uF  [3528-21_EIA]
C90  0.1uF  [0402_1005_Metric]
C91  10uF  [0805_2012_Metric]
C92  1uF  [0603_1608_Metric]
C93  0.1uF  [0402_1005_Metric]
C94  0.01uF  [0402_1005_Metric]
C95  0.01uF  [0402_1005_Metric]
D3  DIODE  [DIODE]
J18  CONN JACK PWR  [3-terminal_thru_hole_power_jack]
JP7  2-Pin Header  [Header_2P]
JP8  2-Pin Header  [Header_2P]
JP9  2-Pin Header  [Header_2P]
JP10  2-Pin Header  [Header_2P]
JP11  2-Pin Header  [Header_2P]
JP12  3-Pin Header  [Header_3P]
L4  15uH  [SMD]
L5  FB 1K@100MHz,0603  [L0603_1608_Metric]
L6  FB 120@100MHz,0603  [L0603_1608_Metric]
L7  FB 120@100MHz,0603  [L0603_1608_Metric]
L8  FB 120@100MHz,0603  [L0603_1608_Metric]
L9  FB 120@100MHz,0603  [L0603_1608_Metric]
L10  FB 120@100MHz,0603  [L0603_1608_Metric]
L11  FB 1K@100MHz,0603  [L0603_1608_Metric]
LED3  0603_red_LED  [d-0603]
R97  0 Ohm,0402  [RES_HDC-0402]
R98  220 Ohm,0402  [RES_HDC-0402]
R99  0 Ohm, 0603  [R0603_1608_Metric]
R100  52.3Kohm  [RES_HDC-0805_2012_metric]
R101  9.53Kohm  [RES_HDC-0805_2012_metric]
R102  3.09Kohm  [RES_HDC-0805_2012_metric]
R103  0 Ohm, 0603  [R0603_1608_Metric]
R104  2.49K  [0603]
R105  100K  [RES_HDC-0603]
R106  1K  [RES_HDC-0603]
R107  0 Ohm,0402  [RES_HDC-0402]
R108  4.99K  [0603]
R109  0 Ohm,0402_open  [RES_HDC-0402]
R110  23.2K  [0402]
R111  100K  [RES_HDC-0603]
R112  12.1K  [0402]
R113  0 Ohm, 0603  [R0603_1608_Metric]
R114  100K  [RES_HDC-0603]
R115  0 Ohm,0402  [RES_HDC-0402]
R116  0 Ohm,0402  [RES_HDC-0402]
R117  0 Ohm, 0603  [R0603_1608_Metric]
U7  LM25576MH/NOPB  [20-TSSOP]
U8  TPS74801DRC  [10-VFDFN_Exposed_Pad]
U9  TPS767D318PWP  [28-HTSSOP]
sheet 07. EXT MSP430
C99  0.1uF  [0402_1005_Metric]
C100  0.1uF  [0402_1005_Metric]
C101  2.2nF  [C-0402]
J19  DIP20 SOCKET - MSP430G2403IN20  [DIP-20]
J20  JTAG-14  [JTAG-14]
J21  2X2-Pin Header  [Header_2X2P]
R118  330ohm  [R-0402]
R119  47Kohm  [R-0603]
S5  SW SMD-8  [SMD-20]
SW3  SPST  [ADTSM31NV]

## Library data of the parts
C1 C2 C5 C8 C10 C24 C32 C48 C50 C53 C56 C61 C65 C69 C73 C77 C79 C83 C90 C93 C102-C104 = CAPACITOR_NON-POL_12: Comments: CAP CER 0.1UF 50V 10% X7R 0402; Digi-Key P/N: 445-6899-1-ND; Distributor: Digi-Key; Distributor PN: 445-6899-1-ND; Lead Free?: YES; Manufacturer: TDK Corporation; Manufacturer PN: CGA2B3X7R1H104K050BB; Part number: CGA2B3X7R1H104K050BB; RoHS Compliant?: YES; Size: 0.039" L x 0.020" W (1.00mm x 0.50mm); Vendor: TDK Corporation
C3 C4 C6 C7 = CAPACITOR_NON-POL_0: Comments: CAP CER 0.033UF 50V 10% X7R 0402; Digi-Key P/N: 445-6896-1-ND; Distributor: Digi-Key; Distributor PN: 445-6896-1-ND; Lead Free?: YES; Manufacturer: TDK Corporation; Manufacturer PN: CGA2B3X7R1H333K050BB; Part number: CGA2B3X7R1H333K050BB; RoHS Compliant?: YES; Size: 0.039" L x 0.020" W (1.00mm x 0.50mm); Vendor: TDK Corporation
C9 C11 C17 C23 C25-C27 C30 C31 C35 C99 C100 = CAPACITOR_NON-POL_0: Comments: CAP CER 0.1UF 50V 10% X7R 0402; Digi-Key P/N: 445-6899-1-ND; Distributor: Digi-Key; Distributor PN: 445-6899-1-ND; Lead Free?: YES; Manufacturer: TDK Corporation; Manufacturer PN: CGA2B3X7R1H104K050BB; Part number: CGA2B3X7R1H104K050BB; RoHS Compliant?: YES; Size: 0.039" L x 0.020" W (1.00mm x 0.50mm); Vendor: TDK Corporation
C12 C66 C80 = CAPACITOR_NON-POL_9: Comments: CAP CER 10UF 16V 10% X7R 1206; Digi-Key P/N: 445-4042-1-ND; Distributor: Digi-Key; Distributor PN: 445-4042-1-ND; Lead Free?: YES; Manufacturer: TDK Corporation; Manufacturer PN: C3216X7R1C106K160AC; Part number: C3216X7R1C106K; RoHS Compliant?: YES; Size: 0.126" L x 0.063" W (3.20mm x 1.60mm); Vendor: TDK
J1 = Automotive_HSD_Connector_2X2_4: Comments: Automotive HSD Connector - Right Angle Plug for PCB.  DO NOT PURCHASE. TI WILL PROVIDE.; Lead Free?: YES; Part number: D4S20B-40ML5-Y; RoHS Compliant?: YES; Vendor: Rosenberger
J2 J7 = CON5_5: Comments: FAKRA-HF PCB RIGHT ANGLE PLUG; Lead Free?: YES; Part number: 59S20X-40ML5-Y_open; RoHS Compliant?: YES; Vendor: Johnson Components
J3-J6 J8 J9 = CON5_5: Comments: End Launch Jack Receptacle - Tab Contact; Digi-Key P/N: J658-ND; Lead Free?: YES; Part number: 142-0701-851; RoHS Compliant?: YES; Vendor: Johnson Components
JP1 JP2 = JUMPER_17: Comments: CONN HEADER VERT .100 2POS 30AU.  DO NOT PURCHASE, DO NOT MOUNT.; Digi-Key P/N: A26542-ND_open; Lead Free?: YES; Part number: 87220-2_open; RoHS Compliant?: YES; Vendor: AMP/Tyco
JP3 = JUMPER_0: Comments: CONN HEADER VERT .100 2POS 30AU. DO NOT PURCHASE. DO NOT POPULATE.; Digi-Key P/N: A26542-ND_open; Lead Free?: YES; Part number: 87220-2_open; RoHS Compliant?: YES; Vendor: AMP/Tyco
L1 L2 = DLW21S_Series_1: Comments: CHOKE COIL COMMON MODE 280MA SMD.  DO NOT PURCHASE. DO NOT POPULATE.; Digi-Key P/N: 490-5134-1-ND_open; Lead Free?: YES; Part number: DLW21SN900HQ2L; RoHS Compliant?: YES; Vendor: Murata
LED1 LED4 = LED_LTST-C230JAKT_2: Comments: LED GREEN CLEAR THIN 0603 SMD; Digi-Key P/N: 160-1446-1-ND; Lead Free?: YES; Part number: LTST-C191KGKT; RoHS Compliant?: YES; Vendor: LITE-ON INC
LED2 = LED_LTST-C230JAKT_2: Comments: LED ORANGE CLR RT ANG SMD; Digi-Key P/N: 160-1477-1-ND; Lead Free?: YES; Part number: LTST-S270KFKT; RoHS Compliant?: YES; Vendor: Lite-On Inc
R1 R2 R75 R98 = R_6: Comments: RES 220 OHM 1/10W 5% 0402 SMD; Digi-Key P/N: P220JCT-ND; Lead Free?: YES; Part number: ERJ-2GEJ221X; RoHS Compliant?: YES; Vendor: Panasonic
R3 R12 R20 R37 R38 R47 R63 R64 R73 R74 R87 R91 R109 R120 = R_6: Comments: RES ZERO OHM 1/16W 5% 0402 SMD.  DO NOT PURCHASE, DO NOT LOAD.; Digi-Key P/N: P0.0JTR-ND_open; Lead Free?: YES; Part number: ERJ-2GEJ0R00X_open; RoHS Compliant?: YES; Vendor: Panasonic
R4 R97 R107 R115 R116 = R_6: Comments: RES ZERO OHM 1/16W 5% 0402 SMD; Digi-Key P/N: P0.0JTR-ND; Lead Free?: YES; Part number: ERJ-2GEJ0R00X; RoHS Compliant?: YES; Vendor: Panasonic
R5 R13 R40 = R_6: Comments: RES 45.3K OHM 1/10W 1% 0402 SMD; Digi-Key P/N: P45.3KLCT-ND; Lead Free?: YES; Part number: ERJ-2RKF4532X; RoHS Compliant?: YES; Vendor: Panasonic
R6 R14 R41 = R_6: Comments: RES 90.9K OHM 1/10W 1% 0402 SMD; Digi-Key P/N: P90.9KLCT-ND; Lead Free?: YES; Part number: ERJ-2RKF9092X; RoHS Compliant?: YES; Vendor: Panasonic
R7 R15 R18 R42 = R_6: Comments: RES 107K OHM 1/10W 1% 0402 SMD; Digi-Key P/N: P107KLCT-ND; Lead Free?: YES; Part number: ERJ-2RKF1073X; RoHS Compliant?: YES; Vendor: Panasonic
R8 R9 R16 R17 R22 R30 R43 R44 R53 = R_6: Comments: RES 113K OHM 1/10W 1% 0402 SMD; Digi-Key P/N: P113KLCT-ND; Lead Free?: YES; Part number: ERJ-2RKF1133X; RoHS Compliant?: YES; Vendor: Panasonic
R10 R45 = R_6: Comments: RES 267K OHM 1/10W 1% 0402 SMD; Digi-Key P/N: P107KLCT-ND; Lead Free?: YES; Part number: ERJ-2RKF1073X; RoHS Compliant?: YES; Vendor: Panasonic
R11 R19 R46 = R_6: Comments: RES 232K OHM 1/10W 1% 0402 SMD; Digi-Key P/N: P232KLCT-ND; Lead Free?: YES; Part number: ERJ-2RKF2323X; RoHS Compliant?: YES; Vendor: Panasonic
R21 R29 R52 = R_6: Comments: RES 182K OHM 1/10W 1% 0402 SMD; Digi-Key P/N: P182KLCT-ND; Lead Free?: YES; Part number: ERJ-2RKF1823X; RoHS Compliant?: YES; Vendor: Panasonic
R23 R31 R54 = R_6: Comments: RES 93.1K OHM 1/10W 1% 0402 SMD; Digi-Key P/N: P93.1KLCT-ND; Lead Free?: YES; Part number: ERJ-2RKF9312X; RoHS Compliant?: YES; Vendor: Panasonic
R24 R32 R55 = R_6: Comments: RES 68.1K OHM 1/10W 1% 0402 SMD; Digi-Key P/N: P68.1KLCT-ND; Lead Free?: YES; Part number: ERJ-2RKF6812X; RoHS Compliant?: YES; Vendor: Panasonic
R25 R27 R33 R35 R56 R58 = R_6: Comments: RES 47.5K OHM 1/10W 1% 0402 SMD; Digi-Key P/N: P47.5KLCT-ND; Lead Free?: YES; Part number: ERJ-2RKF4752X; RoHS Compliant?: YES; Vendor: Panasonic
R26 R34 R57 = R_6: Comments: RES 31.6K OHM 1/10W 1% 0402 SMD; Digi-Key P/N: P31.6KLCT-ND; Lead Free?: YES; Part number: ERJ-2RKF3162X; RoHS Compliant?: YES; Vendor: Panasonic
R28 R36 R59 = R_6: Comments: RES 40.2K OHM 1/10W 1% 0402 SMD; Digi-Key P/N: P40.2KLCT-ND; Lead Free?: YES; Part number: ERJ-2RKF4022X; RoHS Compliant?: YES; Vendor: Panasonic
R48-R50 R65 = R_6: Comments: RES 49.9 OHM 1/10W 1% 0402 SMD. DO NOT PURCHASE. DO NOT POPULATE.; Digi-Key P/N: P49.9LCT-ND_open; Lead Free?: YES; Part number: ERJ-2RKF49R9X_open; RoHS Compliant?: YES; Vendor: Panasonic
R60-R62 R76 R77 = R_7: Comments: RES 10.0K OHM 1/10W 1% 0603 SMD; Digi-Key P/N: P10.0KHCT-ND; Lead Free?: YES; Part number: ERJ-3EKF1002V; RoHS Compliant?: YES; Vendor: Panasonic
S1 S2 S4 S5 = SW_SMD-8_1: Comments: SWITCH TAPE SEAL 8 POS SMD; Digi-Key P/N: CT2198MST-ND; Lead Free?: YES; Part number: 219-8MST; RoHS Compliant?: YES; Vendor: CTS Electrocomponents
S3 = SW_DIP-8_19: Comments: SWITCH DIP EXTENDED SEALED 3POS; Digi-Key P/N: GH7182-ND; Lead Free?: YES; Part number: 78B03ST; RoHS Compliant?: YES; Vendor: Grayhill
SW1-SW3 = SW_PUSHBUTTON-SPST: Comments: SWITCH TACT; Digi-Key P/N: ADTSM31NV-ND; Lead Free?: YES; ROHS Compliant?: YES; Vendor: APEM Components
U1 = DS90UH928Q_3: Comments: DS90UH948Q. DO NOT PURCHASE. TI WILL SUPPLY.; Vendor: TI
C13 C89 = CAPACITOR_POL_1: Comments: CAPACITOR TANT 2.2UF 20V 10% SMD; Digi-Key P/N: 399-3714-1-ND; Lead Free?: YES; Part number: T491B225K020AT; RoHS Compliant?: YES; Vendor: KEMET
C14 C47 C55 C60 C64 C68 C72 C76 C82 C92 = CAPACITOR_NON-POL_10: Comments: CAP CER 1UF 25V 10% X7R 0603; Digi-Key P/N: 445-6931-1-ND; Distributor: Digi-Key; Distributor PN: 445-6931-1-ND; Lead Free?: YES; Manufacturer: TDK Corporation; Manufacturer PN: CGA3E1X7R1E105K080AC; Part number: CGA3E1X7R1E105K080AC; RoHS Compliant?: YES; Size: 0.063" L x 0.031" W (1.60mm x 0.80mm); Vendor: TDK
C15 C44 C51 C57 C58 C62 C70 C74 C78 C84-C87 C94 C95 = CAPACITOR_NON-POL_11: Comments: CAP CER 10000PF 50V 10% X7R 0402; Digi-Key P/N: 490-4762-1-ND; Distributor: Digi-Key; Distributor PN: 490-4762-1-ND; Lead Free?: Lead Free; Manufacturer: Murata Electronics North America; Manufacturer PN: GCM155R71H103KA55D; Part number: GCM155R71H103KA55D; RoHS Compliant?: YES; Size: 0.039" L x 0.020" W (1.00mm x 0.50mm); Vendor: Murata Electronics North America
C16 C88 = CAPACITOR_POL_1: Comments: CAP TANTALUM 22UF 25V 20% SMD; Digi-Key P/N: 493-2391-1-ND; Lead Free?: YES; Part number: F931E226MNC; RoHS Compliant?: YES; Vendor: nichicon
C18 C21 = CAP_NP: Comments: CAP CER 220PF 50V 10% X7R 0603; Descriptiopn: CAP CER 220PF 50V 10% X7R 0603; Dig-Key P/N: 445-1306-1-ND; Digi-Key P/N: 445-1306-1-ND; Part Number: C1608X7R1H221K; Voltage: 50V
C19 C20 = C: Comments: CAP CER 30PF 50V 5% NP0 0603; Descriptiopn: CAP CER 30PF 50V 5% NP0 0603; Dig-Key P/N: 445-5054-1-ND; Digi-Key P/N: 445-5054-1-ND; Part number: C1608C0G1H300J; Vendor: TDK
C22 = CAP_NP: Comments: CAP CER 2200PF 50V 10% X7R 0603; Descriptiopn: CAP CER 2200PF 50V 10% X7R 0603; Dig-Key P/N: 445-1309-1-ND; Digi-Key P/N: 445-1309-1-ND; Part Number: C1608X7R1H222K; Vendor: TDK; Voltage: 50V
C28 C46 C49 C52 C63 = CAPACITOR_NON-POL_12: Comments: CAP CER 4.7UF 16V 10% X7R 0805; Digi-Key P/N: 490-4522-1-ND; Distributor: Digi-Key; Distributor PN: 490-4522-1-ND; Lead Free?: Lead Free; Manufacturer: Murata Electronics North America; Manufacturer PN: GRM21BR71C475KA73L; RoHS Compliant?: YES; Size: 0.079" L x 0.049" W (2.00mm x 1.25mm)
C29 = C: Comments: CAP CER 0.47UF 50V 10% X7R 0603; Descriptiopn: CAP CER 0.47UF 50V 10% X7R 0603; Dig-Key P/N: 445-5952-1-ND; Digi-Key P/N: 445-5952-1-ND; Part number: C1608X7R1H474K; Vendor: TDK
D1 = DIODE_ZENER: Comments: DIODE ZENER 7.5V 3W SMB; Distributor: Digi-Key; Distributor PN: 1SMB5922B13DICT-ND; ICA_MFR_NAME: ON SEMICONDUCTOR; ICA_PARTNUM: $$1184199$$1SMB5922BT3; Manufacturer: Diodes Inc; Manufacturer PN: 1SMB5922B-13; Part Number: TMP-14; Size: SMB
F1 = FUSE: Comments: PTC RESET 15V .500A SMD 1206; Descriptiopn: PTC RESET 15V .500A SMD 1206; Digi-Key P/N: F3733CT-ND; Distributor: Digi-Key; Distributor PN: F3733CT-ND; Manufacturer: Littelfuse Inc; Manufacturer PN: 1206L050/15YR; Part number: 1206L050/15YR; Vendor: Littelfuse Inc
J10 = mini_B_USB_5pin_5: Comments: CONN RECEPT MINI USB2.0 5POS.; Descriptiopn: CONN RECEPT MINI USB2.0 5POS.; Digi-Key P/N: H2959CT-ND; Lead Free?: YES; Part number: UX60-MB-5ST; RoHS Compliant?: YES; Vendor: Hirose
J11 = HEADER_7X2: Comments: CONN HEADER .100 DUAL STR 14POS.  DO NOT PURCHASE. DO NOT POPULATE.; Descriptiopn: CONN HEADER .100 DUAL STR 14POS.  DO NOT PURCHASE. DO NOT POPULATE.; Dig-Key P/N: S2211E-07-ND_open; Digi-Key P/N: S2211E-07-ND_open; Part number: PBC07DFAN_open; Vendor: Sullins
J12 = HEADER_5X2: Comments: CONN HEADER .100 DUAL STR 10POS; Descriptiopn: CONN HEADER .100 DUAL STR 10POS; Digi-Key P/N: S2211E-05-ND; Distributor: Digi-Key; Distributor PN: S2211E-05-ND; Lead Free?: YES; Manufacturer: Sullins Connector Solutions; Manufacturer PN: PBC05DFAN; Part number: PBC05DFAN; RoHS Compliant?: YES; Vendor: Sullins Connector Solutions
JP4 JP6-JP11 = JUMPER_0: Comments: CONN HEADER VERT .100 2POS 30AU; Digi-Key P/N: A26542-ND; Lead Free?: YES; Part number: 87220-2; RoHS Compliant?: YES; Vendor: AMP/Tyco
L3 = INDUCTOR_1: Comments: FERRITE BEAD 60 OHM 0603; Digi-Key P/N: 587-1873-1-ND; Distributor: Digi-Key; Distributor PN: 587-1873-1-ND; Lead Free?: YES; Manufacturer: Taiyo Yuden; RoHS Compliant?: YES; Vendor: Taiyo Yuden
Q1 = NDS355N_SOT: Comments: MOSFET N-CH 50V 220MA SOT-23; Descriptiopn: MOSFET, Nch, 50V, 0.22A, 3.5 Ohm; Dig-Key P/N: BSS138CT-ND; Digi-Key P/N: BSS138CT-ND; Vendor: Fairchild
R66 = R: Comments: RES 33 OHM 1/10W 5% 0603 SMD; Descriptiopn: RES 33 OHM 1/10W 5% 0603 SMD; Digi-Key P/N: P33GCT-ND; Part number: ERJ-3GEYJ330V; Vendor: Panasonic; size: 0603
R67 = R: Comments: RES 33 OHM 1/10W 5% 0603 SMD; Descriptiopn: RES 33 OHM 1/10W 5% 0603 SMD; Dig-Key P/N: P33GCT-ND; Digi-Key P/N: P33GCT-ND; Part number: ERJ-3GEYJ330V; Vendor: Panasonic; size: 0603
R68 R99 R103 R113 R117 = R_1: Comments: RES 0.0 OHM 1/10W JUMP 0603 SMD; Digi-Key P/N: P0.0GTR-ND; Distributor: Digi-Key; Distributor PN: P0.0GTR-ND; Lead Free?: YES; Manufacturer: Panasonic Electronic Components; Manufacturer PN: ERJ-3GEY0R00V; Part number: ERJ-3GEY0R00V; RoHS Compliant?: YES; Size: Jumper; Vendor: Panasonic
R69 R78 R79 = R: Comments: RES 1.5K OHM 1/10W 5% 0603 SMD; Descriptiopn: RES 1.5K OHM 1/10W 5% 0603 SMD; Dig-Key P/N: P1.5KGCT-ND; Digi-Key P/N: P1.5KGCT-ND; Part number: ERJ-3GEYJ152V; Vendor: Panasonic
R70 R72 = R: Comments: RES 33K OHM 1/10W 5% 0603 SMD; Descriptiopn: RES 33K OHM 1/10W 5% 0603 SMD; Dig-Key P/N: P33KGCT-ND; Digi-Key P/N: P33KGCT-ND; Part number: ERJ-3GEYJ333V; Vendor: Panasonic
R71 = R: Comments: RES 1.2M OHM 1/10W 5% 0603 SMD; Descriptiopn: RES 1.2M OHM 1/10W 5% 0603 SMD; Dig-Key P/N: P1.2MGCT-ND; Digi-Key P/N: P1.2MGCT-ND; Part number: ERJ-3GEYJ125V; Vendor: Panasonic
U2 = LP3982IMM-ADJ_2: Comments: IC REG LDO 3.3V 0.5A 8SON; Digi-Key P/N: IC REG LDO 3.3V 0.5A 8SON; Distributor: Digi-Key; Distributor PN: 296-24854-1-ND; Lead Free?: YES; Manufacturer: Texas Instruments; ROHS Compliant?: YES; Vendor: Texas Instruments
U3 = TPD4E004DRY: Comments: IC 4CH ESD-PROT ARRAY 6-SON; Descriptiopn: IC 4CH ESD-PROT ARRAY 6-SON; Dig-Key P/N: 296-23618-1-ND; Digi-Key P/N: 296-23618-1-ND; Part number: TPD4E004DRYR; Vendor: Texas Instruments
U4 = MSP430F5529IPN_0: Comments: IC MCU 16BIT 128K FLASH 80LQFP; Descriptiopn: IC MCU 16BIT 128K FLASH 80LQFP; Dig-Key P/N: 296-27306-1-ND; Digi-Key P/N: 296-27306-1-ND; Vendor: Texas Instruments
U5 = CD40109BMS_1: Comments: IC 6BIT NON-INV TRANSLTR 16TSSOP; Digi-Key P/N: 296-23759-1-ND; Distributor: Digi-Key; Distributor PN: 296-23759-1-ND; ICA_MFR_NAME: TEXAS INSTRUMENTS INC; ICA_PARTNUM: $$1596387$$CD40109BE; Manufacturer: Texas Instruments; Manufacturer PN: TXB0106PWR; Part Number: TXB0106PWR; Vendor: Texas Instruments
U6 = PCA9306_0: Comments: IC VOLT LEVEL TRANSLATOR 8-VSSOP; Descriptiopn: IC VOLT LEVEL TRANSLATOR 8-VSSOP; Dig-Key P/N: 296-17988-1-ND; Digi-Key P/N: 296-17988-1-ND; Distributor: Digi-Key; Distributor PN: 296-28109-2-ND; Manufacturer: Texas Instruments; Part Number: PCA9306DCUR; Vendor: TI
Y1 = CRYSTAL: Comments: CRYSTAL 24.000MHZ 20PF SMD; Descriptiopn: CRYSTAL 24.000MHZ 20PF SMD; Dig-Key P/N: XC1255CT-ND; Digi-Key P/N: XC1255CT-ND; Part number: ECS-240-20-5PX-TR; Vendor: ECS
C33 C34 = CAPACITOR_NON-POL_3: Comments: CAP CERAMIC 4.7PF 25V C0G 0402; Digi-Key P/N: PCC2260CT-ND; Lead Free?: YES; Part number: ECD-G0E4R7C; RoHS Compliant?: YES; Vendor: Panasonic
J13 = IDC_1_x_4_2: Comments: CONN HEADER 4POS .100 VERT GOLD; Digi-Key P/N: WM2702-ND; Lead Free?: YES; Part number: 22-11-2042; RoHS Compliant?: YES; Vendor: Molex/Waldom Electronics Corp
J14 = HEADER_7X2: Comments: CONN HEADER .100 DUAL STR 14POS; Descriptiopn: CONN HEADER .100 DUAL STR 14POS; Dig-Key P/N: S2211E-07-ND; Digi-Key P/N: S2211E-07-ND; Part number: PBC07DFAN; Vendor: Sullins
J15 J16 = JUMPER_14: Comments: CONN HEADER 20 POS STRGHT GOLD.; Digi-Key P/N: MHC20K-ND; Part number: N2520-6002RB; Vendor: 3M
J17 = JUMPER_1: Comments: CONN HEADER .100 DUAL STR 20POS; Digi-Key P/N: S2211E-10-ND; Lead Free?: YES; Part number: PBC10DFAN; RoHS Compliant?: YES; Vendor: Sullins Connector Solutions
JP5 JP12 = JUMPER_13: Comments: CONN HEADER VERT .100 3POS 15AU; Digi-Key P/N: A26545-ND; Lead Free?: YES; Part number: 87224-3; RoHS Compliant?: YES; Vendor: Tyco
R80 R86 R88-R90 R92-R96 = 0201_size_pads_2: Comments: RES 100 OHM 1/10W 5% 0402 SMD. DO NOT PURCHASE. DO NOT POPULATE.; Digi-Key P/N: P100JCT-ND_open; Lead Free?: YES; Part number: ERJ-2GEJ101X_open; RoHS Compliant?: YES; Vendor: Panasonic; size: 0402
R81 R82 = R_2: Comments: RES 4.7K OHM 1/10W 5% 0603 SMD; Digi-Key P/N: P4.7KGCT-ND; Lead Free?: YES; Part number: ERJ-3GEYJ472V; RoHS Compliant?: YES; Vendor: Panasonic; size: 0603
R83-R85 = R_3: Comments: RES ZERO OHM 1/16W 5% 0402 SMD; Digi-Key P/N: P0.0JTR-ND; Lead Free?: YES; Part number: ERJ-2GEJ0R00X; RoHS Compliant?: YES; Vendor: Panasonic
TP1-TP12 = TEST_POINT: Comments: TEST POINT. NOT A COMPONENT
C36 = CAPACITOR_NON-POL_5: Comments: CAP 22000PF 50V CERAMIC X7R 0805; Digi-Key P/N: 399-1163-1-ND; Lead Free?: YES; Part number: C0805C223K5RACTU; RoHS Compliant?: YES; Vendor: Kemet
C37 = CAPACITOR_NON-POL_5: Comments: CAP CER 10UF 25V 20% X7R 1210; Digi-Key P/N: 445-1434-1-ND; Distributor: Digi-Key; Distributor PN: 445-1434-1-ND; Lead Free?: YES; Manufacturer: TDK Corporation; Manufacturer PN: C3225X7R1E106M250AC; Part number: C3225X7R1E106M; RoHS Compliant?: YES; Size: 0.126" L x 0.098" W (3.20mm x 2.50mm); Vendor: TDK Corporation
C38 = CAPACITOR_POL_1: Comments: CAP 100UF 8V SPEC POLYMER SMD; Digi-Key P/N: PCE3601CT-ND; Lead Free?: YES; Part number: EEF-UD0K101R; RoHS Compliant?: YES; Vendor: Panasonic
C39 = CAPACITOR_POL_1: Comments: CAP 270UF 10V ELECT POLY SMD; Digi-Key P/N: 565-3068-1-ND; Lead Free?: YES; Part number: APXA100ARA271MHC0G; RoHS Compliant?: YES; Vendor: United Chemi-Con
C40 C41 = CAPACITOR_NON-POL_11: Comments: CAP CER 100UF 6.3V X5R 1210; Digi-Key P/N: 587-1387-1-ND; Lead Free?: YES; Part number: JMK325BJ107MM-T; RoHS Compliant?: YES; Vendor: Taiyo Yuden
C42 = CAPACITOR_NON-POL_5: Comments: CAP CERAMIC 180PF 50V NP0 0805; Digi-Key P/N: 311-1114-1-ND; Lead Free?: YES; Part number: CC0805JRNP09BN181; RoHS Compliant?: YES; Vendor: Yageo
C43 = CAPACITOR_NON-POL_5: Comments: CAP CERM 150PF 5% 50V NP0 0805; Digi-Key P/N: 478-1318-1-ND; Lead Free?: YES; Part number: 08055A151JAT2A; RoHS Compliant?: YES; Vendor: AVX Corporation
C45 = CAPACITOR_NON-POL_5: Comments: CAP 560PF 50V CERAMIC X7R 0805; Digi-Key P/N: 311-1125-1-ND; Lead Free?: YES; Part number: CC0805KRX7R9BB561; RoHS Compliant?: YES; Vendor: Yageo
C54 C59 C67 C71 C75 C81 C91 = CAPACITOR_NON-POL_12: Comments: CAP CER 10UF 6.3V 10% X7R 0805; Digi-Key P/N: 587-3383-1-ND; Distributor: Digi-Key; Distributor PN: 587-3388-1-ND; Lead Free?: Lead Free; Manufacturer: Taiyo Yuden; Manufacturer PN: JMK212AB7106KGHT; Part number: JMK212AB7106KGHT; RoHS Compliant?: YES; Size: 0.079" L x 0.049" W (2.00mm x 1.25mm); Vendor: Taiyo Yuden
D3 = DIODE_2: Comments: DIODE SCHOTTKY 3A 40V SMA; Digi-Key P/N: B340A-FDICT-ND; Lead Free?: YES; Part number: B340A-13-F; RoHS Compliant?: YES; Vendor: Diodes Inc
J18 = CONN_JACK_PWR: Comments: CONN POWERJACKCONN POWER JACK 2.1MM; Digi-Key P/N: CP-002A-ND; Part number: PJ-002A; Vendor: CUI Inc
L4 = INDUCTOR: Comments: INDUCTOR POWER 15UH SMD; Digi-Key P/N: SDR1806-150MLCT-ND; Lead Free?: YES; Part number: SDR1806-150ML; RoHS Compliant?: YES; Vendor: Bourns Inc.
L5 L11 = INDUCTOR: Comments: FERRITE CHIP BEAD 1000 OHM 0603; Digi-Key P/N: 445-8694-1-ND; Distributor: Digi-Key; Distributor PN: 445-8694-1-ND; Lead Free?: YES; Manufacturer: TDK Corporation; Manufacturer PN: MPZ1608S102A; Part number: MPZ1608S102A; RoHS Compliant?: YES; Vendor: TDK Corporation
L6-L10 = INDUCTOR: Comments: FILTER CHIP 120 OHM 3A 0603; Digi-Key P/N: 490-3996-1-ND; Distributor: Digi-Key; Distributor PN: 490-3996-1-ND; Lead Free?: YES; Manufacturer: Murata Electronics North America; Manufacturer PN: BLM18SG121TN1D; Part number: BLM18SG121TN1D; RoHS Compliant?: YES; Vendor: Murata Electronics North America
LED3 = LED_LTST-C230JAKT_2: Comments: LED SUPER RED CLEAR 0603 SMD; Digi-Key P/N: 160-1436-1-ND; Lead Free?: YES; Part number: LTST-C190KRKT; RoHS Compliant?: YES; Vendor: LITE-ON INC
R100 = R_7: Comments: RES 52.3K OHM 1/8W 1% 0805 SMD; Digi-Key P/N: P52.3KCCT-ND; Lead Free?: YES; Part number: ERJ-6ENF5232V; RoHS Compliant?: YES; Vendor: Panasonic
R101 = R_7: Comments: RES 9.53K OHM 1/8W .1% 0805 SMD; Digi-Key P/N: RG20P9.53KBCT-ND; Lead Free?: YES; Part number: RG2012P-9531-B-T5; RoHS Compliant?: YES; Vendor: Panasonic
R102 = R_7: Comments: RES 3.09K OHM 1/8W 1% 0805 SMD; Digi-Key P/N: P3.09KCCT-ND; Lead Free?: YES; Part number: ERJ-6ENF3091V; RoHS Compliant?: YES; Vendor: Panasonic
R104 = R_7: Comments: RES 2.49K OHM 1/10W 1% 0603 SMD; Digi-Key P/N: P2.49KHTR-ND; Distributor: Digi-Key; Distributor PN: P2.49KHTR-ND; Lead Free?: YES; Manufacturer: Panasonic Electronic Components; Manufacturer PN: ERJ-3EKF2491V; Part number: ERJ-3EKF2491V; RoHS Compliant?: YES; Vendor: Panasonic
R105 R111 R114 = R_7: Comments: RES 100K OHM 1/10W 1% 0603 SMD; Digi-Key P/N: P100KHCT-ND; Lead Free?: YES; Part number: ERJ-3EKF1003V; RoHS Compliant?: YES; Vendor: Panasonic
R106 = R_7: Comments: RES 1.0K OHM 1/10W 1% 0603 SMD; Digi-Key P/N: P1.00KHCT-ND; Lead Free?: YES; Part number: ERJ-3EKF1001V; RoHS Compliant?: YES; Vendor: Panasonic
R108 = R_7: Comments: RES 4.99K OHM 1/10W 1% 0603 SMD; Digi-Key P/N: P4.99KHTR-ND; Distributor: Digi-Key; Distributor PN: P4.99KHTR-ND; Lead Free?: YES; Manufacturer: Panasonic Electronic Components; Manufacturer PN: ERJ-3EKF4991V; Part number: ERJ-3EKF4991V; RoHS Compliant?: YES; Vendor: Panasonic Electronic Components
R110 = R_7: Comments: RES 23.2K OHM 1/10W 1% 0402 SMD; Descriptiopn: RES 23.2K OHM 1/10W 1% 0402 SMD; Distributor: Digi-Key; Distributor PN: P23.2KLCT-ND; Lead Free?: YES; Manufacturer: Panasonic Electronic Components; Manufacturer PN: ERJ-2RKF2322X; RoHS Compliant?: YES; Size: R0402_1005_Metric; Vendor: Panasonic
R112 = R_7: Comments: RES 12.1K OHM 1/10W 1% 0402 SMD; Descriptiopn: RES 12.1K OHM 1/10W 1% 0603 SMD; Distributor: Digi-Key; Distributor PN: P12.1KLCT-ND; Lead Free?: YES; Manufacturer: Panasonic Electronic Components; Manufacturer PN: ERJ-2RKF1212X; RoHS Compliant?: YES; Size: R0402_1005_Metric
U7 = PKG_20_TSSOP_EP_0: Comments: IC BUCK SYNC ADJ 3A 20TSSOP; Digi-Key P/N: LM25576MH-ND; Lead Free?: YES; RoHS Compliant?: YES; Vendor: National Semiconductor
U8 = TPS62052_MSOP_3: Comments: IC REG LDO ADJ 1.5A 10SON; Descriptiopn: IC REG LDO ADJ 1.5A 10SON; Digi-Key P/N: 296-27072-1-ND; Distributor: Digi-Key; Distributor PN: 296-27072-1-ND; ICA_MFR_NAME: TEXAS INSTRUMENTS INC; ICA_PARTNUM: $$2197869$$TPS62052DGSR; Lead Free?: Lead Free; Manufacturer: Texas Instruments; Manufacturer PN: TPS74801DRCT; Part Number: TMP-15; Size: 10-SON (3x3); Vendor: Texas Instruments
U9 = LM2640_SO_8: Comments: IC REG LDO 1.8V/3.3V 1A 28HTSSOP; Digi-Key P/N: 296-2741-5-ND; Distributor: Digi-Key; Distributor PN: 296-2741-5-ND; ICA_MFR_NAME: NATIONAL SEMICONDUCTOR CORP; ICA_PARTNUM: $$914419$$LM2640MTC-ADJ; Lead Free?: Lead Free; Manufacturer: Texas Instruments; Size: 28-TSSOP (0.173", 4.40mm Width) Exposed Pad; Vendor: Texas Instruments
C101 = CAPACITOR_NON-POL_7: Comments: CAP CER 2200PF 50V X7R AUTO 0402; Digi-Key P/N: 445-5606-1-ND; Lead Free?: YES; Part number: CGA2B2X7R1H222K; RoHS Compliant?: YES; Vendor: TDK Corporation
J19 = DIP8_SOCKET_4: Comments: SOCKET IC OPEN FRAME 20POS .3"; Digi-Key P/N: 3M5477-ND
J20 = DIP8_SOCKET_5: Comments: CONN HEADER LOW-PRO 14POS GOLD; Digi-Key P/N: HRP14H-ND; Part Number: AWHW14G-0202-T-R
J21 = JUMPER_20: Comments: CONN HEADER VERT DUAL 4POS GOLD; Digi-Key P/N: A26567-ND; Lead Free?: YES; Part number: 87227-2; RoHS Compliant?: YES; Vendor: TEC
R118 = ERJ-1GE0R00C_2: Comments: RES 330 OHM 1/10W 1% 0402 SMD; Digi-Key P/N: P330LCT-ND; Lead Free?: YES; Part number: ERJ-2RKF3300X; RoHS Compliant?: YES; Vendor: Panasonic; size: 0402
R119 = ERJ-1GE0R00C_2: Comments: RES 47K OHM 1/16W .1% 0603 SMD; Digi-Key P/N: P47KDBCT-ND; Lead Free?: YES; Part number: ERA-3AEB473V; RoHS Compliant?: YES; Vendor: Panasonic; size: 0603

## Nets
+5V: C46.1 C47.1 C48.1 C52.1 C63.1 C64.1 JP7.2 R98.2 R99.2 R105.2 R107.1 U8.1(IN) U8.2(IN) U8.4(BIAS) U9.5(1IN) U9.6(1IN) U9.11(2IN) U9.12(2IN)
VBUS: C16.1 D1.2(C) F1.2 L3.2 U4.65(VBUS)
VDD12: JP8.1 L6.1 L7.1 L8.1 L9.1 L10.1 R103.2
VDD12_LVDS: C81.1 C82.1 C83.1 C84.1 C85.1 L10.2 U1.20(VDD12_LVDS) U1.32(VDDP12_LVDS)
VDD12_Pin33: C59.1 C60.1 C61.1 C62.1 L6.2 R3.1
VDD18: JP5.3 JP9.1 JP12.1 R113.2
VDD33: C99.2 C100.2 J19.1(DVCC) J20.3 JP5.1 JP10.1 JP12.3 L5.1 R117.2 R119.2
VDD33_UC: C24.1 C26.2 C27.2 C28.1 C31.2 JP4.1 LED4.2(ANODE) R68.1 R72.2 R77.1 R78.2 R79.2 U4.11(AVCC1) U4.18(DVCC1) U4.50(DVCC2) U5.15(VCCB) U6.7(VCCB)
VDD33c: C54.1 C55.1 C56.1 C57.1 C58.1 L5.2 R5.1 R6.1 R7.1 R8.1 R9.1 R10.1 R11.1 R12.1 R13.1 R14.1 R15.1 R16.1 R17.1 R18.1 R19.1 R20.1 R40.1 R41.1 R42.1 R43.1 R44.1 R45.1 R46.1 R47.1 U1.31(VDD33_B) U1.56(VDD33_A)
VDD_12.0V_EXTERNAL: C37.1 J18.1 U7.3(VIN) U7.4(VIN)
VDD_I2C: C30.2 JP5.2 JP6.1 R81.1 R82.1 R83.2 U6.3(VDDA)
VDDIO: C25.2 C88.1 C89.1 C90.2 JP6.2 JP11.1 JP12.2 L11.1 R60.2 R61.2 R62.2 R76.2 R87.2 R91.2 U5.2(VCCA)
VDDIOc: C91.1 C92.1 C93.1 C94.1 L11.2 U1.3(VDDIO)
VDDL12c: C75.1 C76.1 C77.1 C78.1 C95.1 L9.2 U1.6(VDDL12_0) U1.44(VDDL12_1)
VDDP12_0: C67.1 C68.1 C69.1 C70.1 C86.1 L7.2 U1.51(VDDP12_CH0) U1.52(VDDR12_CH0)
VDDP12_1: C71.1 C72.1 C73.1 C74.1 C87.1 L8.2 U1.57(VDDR12_CH1) U1.60(VDDP12_CH1)
VSS: C1.1 C2.1 C5.1 C8.1 C10.1 C12.2 C13.2 C14.2 C15.2 C16.2 C17.1 C18.2 C19.2 C20.2 C21.2 C22.2 C23.1 C24.2 C25.1 C26.1 C27.1 C28.2 C29.2 C30.1 C31.1 C32.2 C33.2 C34.2 C35.2 C37.2 C38.2 C39.2 C40.2 C41.2 C43.2 C44.2 C46.2 C47.2 C48.2 C49.2 C50.2 C51.2 C52.2 C53.2 C54.2 C55.2 C56.2 C57.2 C58.2 C59.2 C60.2 C61.2 C62.2 C63.2 C64.2 C65.1 C66.2 C67.2 C68.2 C69.2 C70.2 C71.2 C72.2 C73.2 C74.2 C75.2 C76.2 C77.2 C78.2 C79.1 C80.2 C81.2 C82.2 C83.2 C84.2 C85.2 C86.2 C87.2 C88.2 C89.2 C90.1 C91.2 C92.2 C93.2 C94.2 C95.2 C99.1 C100.1 C101.2 C102.1 C103.1 C104.1 D1.1(A) J1.5 J1.6 J1.7 J1.8 J2.2 J2.3 J2.4 J2.5 J3.2 J3.3 J3.4 J3.5 J4.2 J4.3 J4.4 J4.5 J5.2 J5.3 J5.4 J5.5 J6.2 J6.3 J6.4 J6.5 J7.2 J7.3 J7.4 J7.5 J8.2 J8.3 J8.4 J8.5 J9.2 J9.3 J9.4 J9.5 J10.5 J10.8 J10.9 J11.9 J12.5 J13.4 J14.1 J14.3 J14.5 J14.7 J14.9 J14.11 J14.13 J15.1 J15.4 J15.5 J15.8 J15.9 J15.12 J15.13 J15.16 J15.17 J15.20 J16.1 J16.4 J16.5 J16.8 J16.9 J16.12 J16.13 J16.16 J16.17 J16.20 J17.1 J17.3 J17.5 J17.7 J17.9 J17.11 J17.13 J17.15 J17.17 J17.19 J18.2 J18.3 J19.20(DVSS) J20.10 J21.1 J21.3 JP1.2 JP2.2 JP3.1 JP4.2 JP8.2 JP9.2 JP10.2 JP11.2 LED1.1(CATHODE) LED2.1(CATHODE) LED3.1(CATHODE) Q1.2(SOURCE) R21.2 R22.2 R23.2 R24.2 R25.2 R26.2 R27.2 R28.2 R29.2 R30.2 R31.2 R32.2 R33.2 R34.2 R35.2 R36.2 R48.2 R49.2 R50.2 R52.2 R53.2 R54.2 R55.2 R56.2 R57.2 R58.2 R59.2 R65.2 R70.2 R71.2 R101.2 R106.1 R108.1 R109.2 R110.1 R115.1 R116.1 S3.4(B3) S3.5(B2) S3.6(B1) S5.1(A1) S5.3(A2) S5.5(A3) S5.7(A4) S5.9(A5) S5.11(A6) S5.13(A7) S5.15(A8) SW1.1 SW3.1 TP1.1 TP2.1 TP3.1 TP4.1 TP5.1 TP6.1 TP7.1 TP8.1 TP9.1 TP10.1 TP11.1 TP12.1 U1.65(DAP) U2.4(GND) U2.9(PWPD) U3.3(GND) U4.14(AVSS1) U4.19(DVSS1) U4.49(DVSS2) U4.61(VSSU) U4.68(AVSS2) U5.9(GND) U6.2(GND) U7.10(AGND) U7.13(PGND) U7.14(PGND) U7.21(DAP) U8.6(GND) U8.11(PwPd) U9.3(1GND) U9.9(2GND) U9.29(PWPD)
AIN_B_0: U4.1(P6.4/CB4/A4)
AIN_B_1: U4.2(P6.5/CB5/A5)
BISTC: J14.4 JP3.2 R61.1 S3.2(A2) U1.4(BISTC/INTB)
BISTEN: J14.2 R62.1 S3.1(A1) U1.5(BISTEN/TESTEN)
CAPI2S: C10.2 U1.2(CAP_I2S)
CLK1+: J15.15 R89.2 U1.36(CLK1+)
CLK1-: J15.14 R89.1 U1.37(CLK1-)
CLK2+: J16.15 R95.2 U1.23(CLK2+)
CLK2-: J16.14 R95.1 U1.24(CLK2-)
D0+: J15.3 R80.2 U1.42(D0+)
D0-: J15.2 R80.1 U1.43(D0-)
D1+: J15.7 R86.2 U1.40(D1+)
D1-: J15.6 R86.1 U1.41(D1-)
D2+: J15.11 R88.2 U1.38(D2+)
D2-: J15.10 R88.1 U1.39(D2-)
D3+: J15.19 R90.2 U1.34(D3+)
D3-: J15.18 R90.1 U1.35(D3-)
D4+: J16.3 R92.2 U1.29(D4+)
D4-: J16.2 R92.1 U1.30(D4-)
D5+: J16.7 R93.2 U1.27(D5+)
D5-: J16.6 R93.1 U1.28(D5-)
D6+: J16.11 R94.2 U1.25(D6+)
D6-: J16.10 R94.1 U1.26(D6-)
D7+: J16.19 R96.2 U1.21(D7+)
D7-: J16.18 R96.1 U1.22(D7-)
D_GPIO0: J14.14 U1.19(D_GPIO0/MOSI)
D_GPIO1: J14.12 U1.18(D_GPIO1/MISO)
D_GPIO2: J14.10 U1.17(D_GPIO2/SPLK)
D_GPIO3: J14.8 U1.16(D_GPIO3/SS)
DM: R66.2 U4.64(PU.1/DM)
DOUT+: C9.2 U1.62(CMLOUTP)
DOUT-: C11.2 U1.63(CMLOUTM)
DP: R67.2 R69.1 U4.62(PU.0/DP)
GPIO0: J17.2 JP2.1 R2.2 U1.7(SDOUT/GPIO0/PASS)
GPIO0/I2C(SDA): J12.1 U4.46(P4.1/PM_UCB1SIMO/PM_UCB1SDA) U6.1(SDA_B)
GPIO1: J17.4 U1.8(SWC/GPIO1)
GPIO1/I2C(SCL): J12.2 U4.47(P4.2/PM_UCB1SOMI/PM_UCB1SCL) U6.8(SCL_B)
GPIO2/SPI(SCLK): J12.3 U4.45(P4.0/PM_UCB1STE/PM_UCA1CLK) U5.12(B4)
GPIO3/PWM2: J12.4 R73.1 U4.33(P2.4/TA2.1)
GPIO4/SPI(SIMO)/UART(TXD): J12.7 U4.52(P4.5/PM_UCA1RXD/PM_UCA1SOMI) U5.11(B5)
GPIO5/SPI(SOMI)/UART(RXD): J12.8 U4.51(P4.4/PM_UCA1TXD/PM_UCA1SIMO) U5.10(B6)
GPIO6/PWM1/SPI(CS): J12.9 U4.29(P2.0/TA1.1) U5.13(B3)
GPIO7/PWM0: J12.10 R74.1 U4.23(P1.2/TA0.1)
GPIO8/ADC3: U4.4(P6.7/CB7/A7)
GPIO9/ADC2: U4.3(P6.6/CB6/A6)
GPIO10/VEREF-: U4.10(P5.1/A9/VREF-/VeREF-)
GPIO11/VEREF+: C23.2 U4.9(P5.0/A8/VREF+/VeREF+)
I2C_SCL: J19.14(SCL) R82.2 R85.1 U1.45(I2C_SCL) U6.5(SCL_A)
I2C_SDA: J19.15(SDA) R81.2 R84.1 U1.46(I2C_SDA) U6.4(SDA_A)
I2S_CLK: J17.18 U1.13(I2S_CLK/GPIO8_REG)
I2S_DA: J17.14 U1.12(I2S_DA/GPIO6_REG)
I2S_DB: J17.12 U1.11(I2S_DB/GPIO5_REG)
I2S_DC: J17.6 U1.10(I2S_DC/GPIO2)
I2S_DD: J17.8 U1.9(I2S_DD/GPIO3)
I2S_WC: J17.16 U1.14(I2S_WC/GPIO7_REG)
IDX: C104.2 S4.2(B1) S4.4(B2) S4.6(B3) S4.8(B4) S4.10(B5) S4.12(B6) S4.14(B7) S4.16(B8) U1.47(IDX)
INTB: J19.9(P2.1) U5.3(A2)
INTB_CTRL: R74.2 U5.14(B2)
LOCK: JP1.1 R1.2 U1.1(LOCK)
MCLK: J17.20 U1.15(MCLK)
MISO: J19.3(P1.1) U5.6(A5)
MODE_SEL0: C102.2 S1.2(B1) S1.4(B2) S1.6(B3) S1.8(B4) S1.10(B5) S1.12(B6) S1.14(B7) S1.16(B8) U1.61(MODE_SEL0)
MODE_SEL1: C103.2 S2.2(B1) S2.4(B2) S2.6(B3) S2.8(B4) S2.10(B5) S2.12(B6) S2.14(B7) S2.16(B8) U1.50(MODE_SEL1)
MOSI: J19.4(P1.2) U5.7(A6)
PDB: C12.1 J19.13(P2.5) R60.1 R120.1 S3.3(A3) SW1.2 U1.48(PDB)
PDB_CTRL: R73.2 U5.16(B1)
PUR: R69.2 R71.1 SW2.1 U4.63(PUR)
RINA+: C3.1 J1.2 L1.3 L1.4 R37.2
RINA-: C4.1 J1.4 L1.1 L1.2 R38.2
RINB+: C6.1 J1.1 L2.3 L2.4 R63.2
RINB-: C7.1 J1.3 L2.1 L2.2 R64.2
RST: C101.1 J19.16(RST) J20.2 J21.2 R119.1 SW3.2
SCLBRD: R79.1 U4.38(P3.1/UCB0SOMI/UCB0SCL)
SDABRD: R78.1 U4.37(P3.0/UCB0SIMO/UCB0SDA)
SPLK: J19.6(P1.4) U5.5(A4)
SS: J19.5(P1.3) U5.4(A3)
SW0: J19.2(P1.0) S5.2(B1)
SW1: J19.7(P1.5) S5.4(B2)
SW2: J19.8(P2.0) S5.6(B3)
SW3: J19.10(P2.2) S5.8(B4)
SW4: J19.19(P2.6) S5.10(B5)
SW5: J19.18(P2.7) S5.12(B6)
SW6: J19.12(P2.4) S5.14(B7)
SW7: J19.11(P2.3) S5.16(B8)
TCK: J11.7 U4.75(PJ.3/TCK)
TDI: J11.3 U4.73(PJ.1/TDI/TCLK)
TDO: J11.1 U4.72(PJ.0/TDO)
TEST: J19.17(TEST) J20.7 J21.4 R118.2
TEST1: J11.8 U4.71(TEST/SBWTCK)
TMS: J11.5 U4.74(PJ.2/TMS)
VUSB: C18.1 SW2.2 U4.66(VUSB)
~RST: C22.1 J11.11 R72.1 U4.76(~RST/NMI/SBWTDIO)
N15364431: C38.1 C39.1 C40.1 C41.1 JP7.1 L4.2 R99.1 R102.1 U7.12(OUT)
N15364577: C36.2 D3.1(CATHODE) L4.1 R97.1 U7.17(SW) U7.18(SW)
N15364585: R97.2 U7.19(PRE)
N15364743: C35.1 U7.1(VCC)
N15364759: C44.1 U7.11(SS)
N15364779: C43.1 U7.9(RAMP)
N15364847: R101.1 U7.8(RT)
N15364875: C42.1 R100.1 R102.2 R106.2 U7.7(FB)
N15364879: C42.2 C45.2 U7.6(COMP)
N15364919: C45.1 R100.2
N15365001: D3.2(ANODE) U7.15(IS_2) U7.16(IS_1)
N15365029: C36.1 U7.20(BST)
N16848563: C29.1 U4.20(VCORE)
N16848714: C21.1 U4.67(V18)
N16849932: J10.3 R67.1 U3.4(IO3)
N16849951: C17.2 F1.1 J10.1 U3.6(VCC)
N16849953: J10.2 R66.1 U3.1(IO1)
N16849991: J10.6 J10.7 R70.1
N16930628: Q1.1(GATE) U4.15(P8.0)
N17059131: J20.8 R118.1
N17075556: C6.2 U1.58(RIN+)
N17075562: C7.2 U1.59(RIN-)
N17075662: C5.2 U1.55(CMF)
N17075712: C3.2 U1.53(RIN0+)
N17075718: C4.2 U1.54(RIN0-)
N17084124: J17.10 R91.1
N17084564: C34.1 J13.2 R85.2
N17084583: C33.1 J13.3 R84.2
N17084590: C32.1 J13.1 R83.1
N17084985: J4.1 R38.1 R50.1
N17084987: J2.1 J3.1 R37.1
N17087573: J9.1 R64.1 R65.1
N17087575: J7.1 J8.1 R63.1
N17097514: R43.2 R55.1 S4.9(A5)
N17097522: R42.2 R54.1 S4.11(A6)
N17097524: R41.2 R53.1 S4.13(A7)
N17097526: R47.2 R59.1 S4.1(A1)
N17097528: R45.2 R57.1 S4.5(A3)
N17097530: R46.2 R58.1 S4.3(A2)
N17097532: R44.2 R56.1 S4.7(A4)
N17097556: R40.2 R52.1 S4.15(A8)
N17103018: C11.1 J6.1 R49.1
N17103031: C9.1 J5.1 R48.1
N17121993: R77.2 U6.6(OE)
N17123672: C19.1 U4.70(P5.3/XT2OUT) Y1.2
N17123682: C20.1 U4.69(P5.2/XT2IN) Y1.1
N17132631: C14.1 L3.1 U2.5(EN) U2.8(IN)
N17133396: C15.1 U2.3(NR/FB)
N17133657: C13.1 R68.2 U2.1(OUT)
N17138963: C2.2 U1.49(CAP_PLL0)
N17143987: C8.2 U1.64(CAP_PLL1)
N17154309: LED2.2(ANODE) R2.1
N17160541: R76.1 U5.8(OE)
N17174458: R3.2 R4.1 U1.33(VDD25_CAP)
N17176193: C1.2 R4.2
N17179271: C49.1 C50.1 R103.1 R104.2 U8.9(OUT) U8.10(OUT)
N17179285: R104.1 R108.2 U8.8(FB)
N17180621: C51.1 U8.7(SS)
N17181839: R105.1 U8.3(PG)
N17182034: C53.1 R107.2 R109.1 U8.5(EN)
N17191311: LED3.2(ANODE) R98.1
N17214938: C79.2 C80.1 R114.1 R117.1 U9.17(2OUT) U9.18(2OUT)
N17214967: C65.2 C66.1 R111.1 R112.1 R113.1 U9.23(1OUT) U9.24(1OUT)
N17217834: R114.2 U9.22(~{2RESET})
N17220662: R111.2 U9.28(~{1RESET})
N17221888: R110.2 R112.2 U9.25(1FB/NC)
N17228595: R116.2 U9.10(~{2EN})
N17228599: R115.2 U9.4(~{1EN})
N17278417: R10.2 R26.1 S1.5(A3)
N17278419: R8.2 R24.1 S1.9(A5)
N17278425: R11.2 R27.1 S1.3(A2)
N17278439: R9.2 R25.1 S1.7(A4)
N17278441: R6.2 R22.1 S1.13(A7)
N17278443: R7.2 R23.1 S1.11(A6)
N17278445: R5.2 R21.1 S1.15(A8)
N17278449: R12.2 R28.1 S1.1(A1)
N17278561: R16.2 R32.1 S2.9(A5)
N17278569: R15.2 R31.1 S2.11(A6)
N17278593: R14.2 R30.1 S2.13(A7)
N17278595: R20.2 R36.1 S2.1(A1)
N17278597: R18.2 R34.1 S2.5(A3)
N17278599: R19.2 R35.1 S2.3(A2)
N17278601: R17.2 R33.1 S2.7(A4)
N17278603: R13.2 R29.1 S2.15(A8)
N17395731: LED1.2(ANODE) R1.1
N17549527: LED4.1(CATHODE) R75.1
N17549528: Q1.3(DRAIN) R75.2
N17585585: J14.6 R87.1
N17653350: R120.2 U5.1(A1)

Not connected (* = marked no-connect by the designer): J10 4; J11 2* 4* 6* 10* 12* 13* 14*; J12 6*; J20 1* 4* 5* 6* 9 11* 12* 13* 14*; U2 2(NC1) 6(NC2) 7(NC3); U3 2(IO2)* 5(IO4)*; U4 5(P7.0/CB8/A12)* 6(P7.1/CB9/A13)* 7(P7.2/CB10/A14)* 8(P7.3/CB11/A15)* 12(P5.4/XIN)* 13(P5.5/XOUT)* 16(P8.1)* 17(P8.2)* 21(P1.0/TA0CLK/ACLK)* 22(P1.1/TA0.0)* 24(P1.3/TA0.2)* 25(P1.4/TA0.3)* 26(P1.5/TA0.4)* 27(P1.6/TA1CLK/CBOUT)* 28(P1.7/TA1.0)* 30(P2.1/TA1.2)* 31(P2.2/TA2CLK/SMCLK)* 32(P2.3/TA2.0)* 34(P2.5/TA2.2)* 35(P2.6/RTCCLK/DMAE0)* 36(P2.7/UCB0STE/UCA0CLK)* 39(P3.2/UCB0CLK/UCA0STE)* 40(P3.3/UCA0TXD/UCA0SIMO)* 41(P3.4/UCA0RXD/UCA0SOMI)* 42(P3.5/TB0.5)* 43(P3.6/TB0.6)* 44(P3.7/TB0OUTH/SVMOUT)* 48(P4.3/PM_UCB1CLK/PM_UCA1STE)* 53(P4.6/PM_NONE)* 54(P4.7/PM_NONE)* 55(P5.6/TB0.0)* 56(P5.7/TB0.1)* 57(P7.4/TB0.2)* 58(P7.5/TB0.3)* 59(P7.6/TB0.4)* 60(P7.7/TB0CLK/MCLK)* 77(P6.0/CB0/A0)* 78(P6.1/CB1/A1)* 79(P6.2/CB2/A2)* 80(P6.3/CB3/A3)*; U7 2(SD)* 5(SYNC)*; U9 1(NC1) 2(NC2) 7(NC3) 8(NC4) 13(NC5) 14(NC6) 15(NC7) 16(NC8) 19(NC9) 20(NC10) 21(NC11) 26(NC12) 27(NC13)

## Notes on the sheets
sheet 1
- Rev 1A
  -Initial version
  Rev 1B
  -Changed R21, R29, R52 to 240K
  -Changed R22, R30, R53 to 196K
  -Changed R23, R31, R54 to 162K
  -Changed R24, R32, R55 to 120K
  -Changed R25, R33, R56 to 100K
  -Changed C3, C4, C6, C7 to 0.033uF
  -Added C102, C103 0.1uF
  -Corrected BOM mfr p/n for: C15, C44, C51, C57, C58, C62, C70, C74, C78, C84, C85, C97
  -Added C86, C87, C95 0.01uF
  -Updated BOM p/n for J14
  Rev 1C
  -Remapped J14 signals for flowthrough
  -Deleted R39, R51
  Rev 1D
  -Connected signal " GPIO5/SPI(SOMI)/UART(RXD) " to the J12
  -Corrected BOM for R105, R111, R114
  -Updated U5, U7 Value to match Part number in BOM
  Rev 1E
  -Added VSS connections to LED1, LED2
  -Updated MODE_SEL0/1 resistors R5-R36
  -Updated IDX resistors R40-R47
  -J17 changed p/n
  -Added R120
  -Updated LED3 p/n
sheet 2
- Board Block Diagram
- Approximate layout of major components/connectors
- J18
- U8
- U9
- U7
- Power
- +12V
  Barrel
- +5V
  Aux
- Options
- I2S Bank
- D_GPIO
- Connector
- PDB
  BISTC
  BISTEN
  INTB
- GPIO0
  GPIO1
  I2S_DA
  I2S_DB
  I2S_DC
  I2S_DD
  I2S_CLK
  I2S_WC
  MCLK
- D_GPIO0
  D_GPIO1
  D_GPIO2
  D_GPIO3
- J10
- J19
- Supply
- VDD33
  VDD12
  VDD18
- VSS
- U2
- J13
- S5
- J2/J3
- U4
- J4
- J15
- SMA /
  FAKRA
- J1
- U1
- SMA
- J16
- J7/J8
- FPDL3+
- 20-pin IDC
- J9
- HSD
- LVDSx+
- J17
- J14
- FPDL3-
- LVDSx-
- J5
- SMA /
  FAKRA
- S4
- DS90UH948Q
  DS90UH940Q
- J6
- S2
- S1
- S3
- 20-pin IDC
- SMA
- LVDSx+
- LVDSx-
- FPDL3+
- HSD
- FPDL3-
- FPD (LVDS) Output
- FPD3 Input
- SDA
- I2C
  Connector
- Status LEDs
- CAD
- SCL
- PASS
- IDx
- USB2ANY
- LOCK
- MODE_SEL[1:0]
- USB
sheet 3
- LAYOUT NOTES:
  1) 4 layer board.
  2) Use standard FR-406 or FR-370HR.
  3) 5% impedance tolerance.
  4) Minimum 4 standoffs on each corner of board.  (0.156 X 4).
- 1
- Primary component side, 1.58 MIL (layer 1)
- 4.5 MIL
- 2
- Ground plane, 1.4 MIL (layer 2)
- 44.2 MIL Core
- 3
- Power plane, 1.4 MIL (layer 3)
- 4.5 MIL
- 4
- Secondary component side, 1.58 MIL (layer 4)
- Core Material
- Prepreg Material
sheet 4
- Layout note: For all differential pairs(CSI-2 and LVDS) in this design follow the guidelines decribed below:
  Route together with controlled differential 100ohm impedance and controlled single ended 50ohm
  impedance. Keep away from other high speed signals. Keep lengths within 5mil of each other. Keep
  traces on layers adjacent to the ground plane. Keep the number of VIAS to minimum. If VIAS are used,
  make it symetrical through all signals. Keep diff pairs separated at least by x3 of the trace width.
  NO STUBS on the signal path, components should be placed such that the signals can routed in
  pass-through manner.
- R3          R4
  948     open        populated
  940     populated   open
- Connect to VSS
- Connect to VSS
- LAYOUT NOTE: L short pin 1 to
  pin 2, short pin 3 and pin 4. Cut
  traces to populate common
  mode filter.
- 100 ohm differential impedance +/-5%.
- 100 ohm differential impedance +/-5%.
- 100 ohm differential impedance +/-5%.
- H
- H
- MODE_SEL0
- MODE_SEL1
- L
- L
- 8
- 7
- 6
- 5
- 4
- 3
- 2
- 1
- 8
- 7
- 6
- 5
- 4
- 3
- 2
- 1
- CMLOUT+
- Layout note: overlay
  footprint for SMA and
  FAKRA connector - signal
  pin 1 on both is the same
  pad
- 0.625"
- 50 ohm
  single
  ended
  impedance
  traces
- 50 ohm
  single ended
  impedance
  traces
- 0.625"
- CMLOUT-
- 50 ohm single ended
  impedance traces
- Silkscreen
  namings
- H
- H
- L
- INTB_IN
- Layout note: overlay
  footprint for SMA and
  FAKRA connector - signal
  pin 1 on both is the same
  pad
- IDX
- 0.625"
- L
- 50 ohm
  single ended
  impedance
  traces
- 78
- 70
- 6C
- 68
- 64
- 60
- 5C
- 58
sheet 5
- 3V3@0.5A UC POWER SUPPLY
- XTAL 24 MHz
- JTAG
- USB2ANY CONNECTOR
- 50 ohm single ended
  impedance traces
- VOLTAGE LEVEL TRANSLATOR
- 50 ohm single ended
  impedance traces
- 50 ohm single ended
  impedance traces
- I2C LEVEL TRANSLATOR
- NOTE: Float p2.3, p2.5, and p2.6 on MSP430 for USB2ANY detection
sheet 6
- 100 ohm diff pair. +/-5%.
  Resistors have to be placed close to U1.
  +/- 1 mil for all inter/intra pairs.
- Place at the board edge
- TP
- 1.12mm
- TX OUT
- Dp
- D0-/CSI1_D3+
- D0+/CSI1_D3-
- 0402 pad
- D1-/CSI1_D2+
- Dn
- D1+/CSI1_D2-
- External I2C connection
- D2-/CSI1_D1+
- D2+/CSI1_D1-
- C1-/CSI1_D0+
- TP
- 1.12mm
- C1+/CSI1_D0-
- D3-/CSI1_C+
- D3+/CSI1_C-
- 50 ohm single ended
  impedance traces
- INT_B
- TESTEN
- SS
- SPLK
- MISO
- MOSI
- SDOUT
- 0.5"
- DC
- SWC
- DD
- 100 ohm diff pair. +/-5%.
  Resistors have to be placed close to U1.
  +/- 1 mil for all inter/intra pairs.
- 50 ohm single ended
  impedance traces
- DB
- DA
- WC
- CLK
- MCLK
- TX OUT
- D4-/CSI0_D3+
- D4+/CSI0_D3-
- D5-/CSI0_D2+
- D5+/CSI0_D2-
- D6-/CSI0_D1+
- D5+/CSI0_D1-
- C2-/CSI0_D0+
- C2+/CSI0_D0-
- D7-/CSI0_C+
- D7+/CSI0_C-
sheet 7
- MAIN
  12V INPUT
  POWER
  CONNECTOR
- 1V2@0.5A POWER SUPPLY
- MAIN POWER
- Layout note: mount
  C38, C39 on top side of
  board.
- Place near pin of U1
- 1V8@1A POWER SUPPLY
  3V3@1A POWER SUPPLY
- Place near pin of U1
- Place near pin of U1
- Place near pin of U1
- Place near pin of U1
- VDDIO External input
- Place near pin of U1
- Place near pin of U1
- VDDIO=VDD18
- VDDIO=VDD33
sheet 8
- RST
- Put RST switch at the bottom edge of the board. Mark down every Netname to the position
